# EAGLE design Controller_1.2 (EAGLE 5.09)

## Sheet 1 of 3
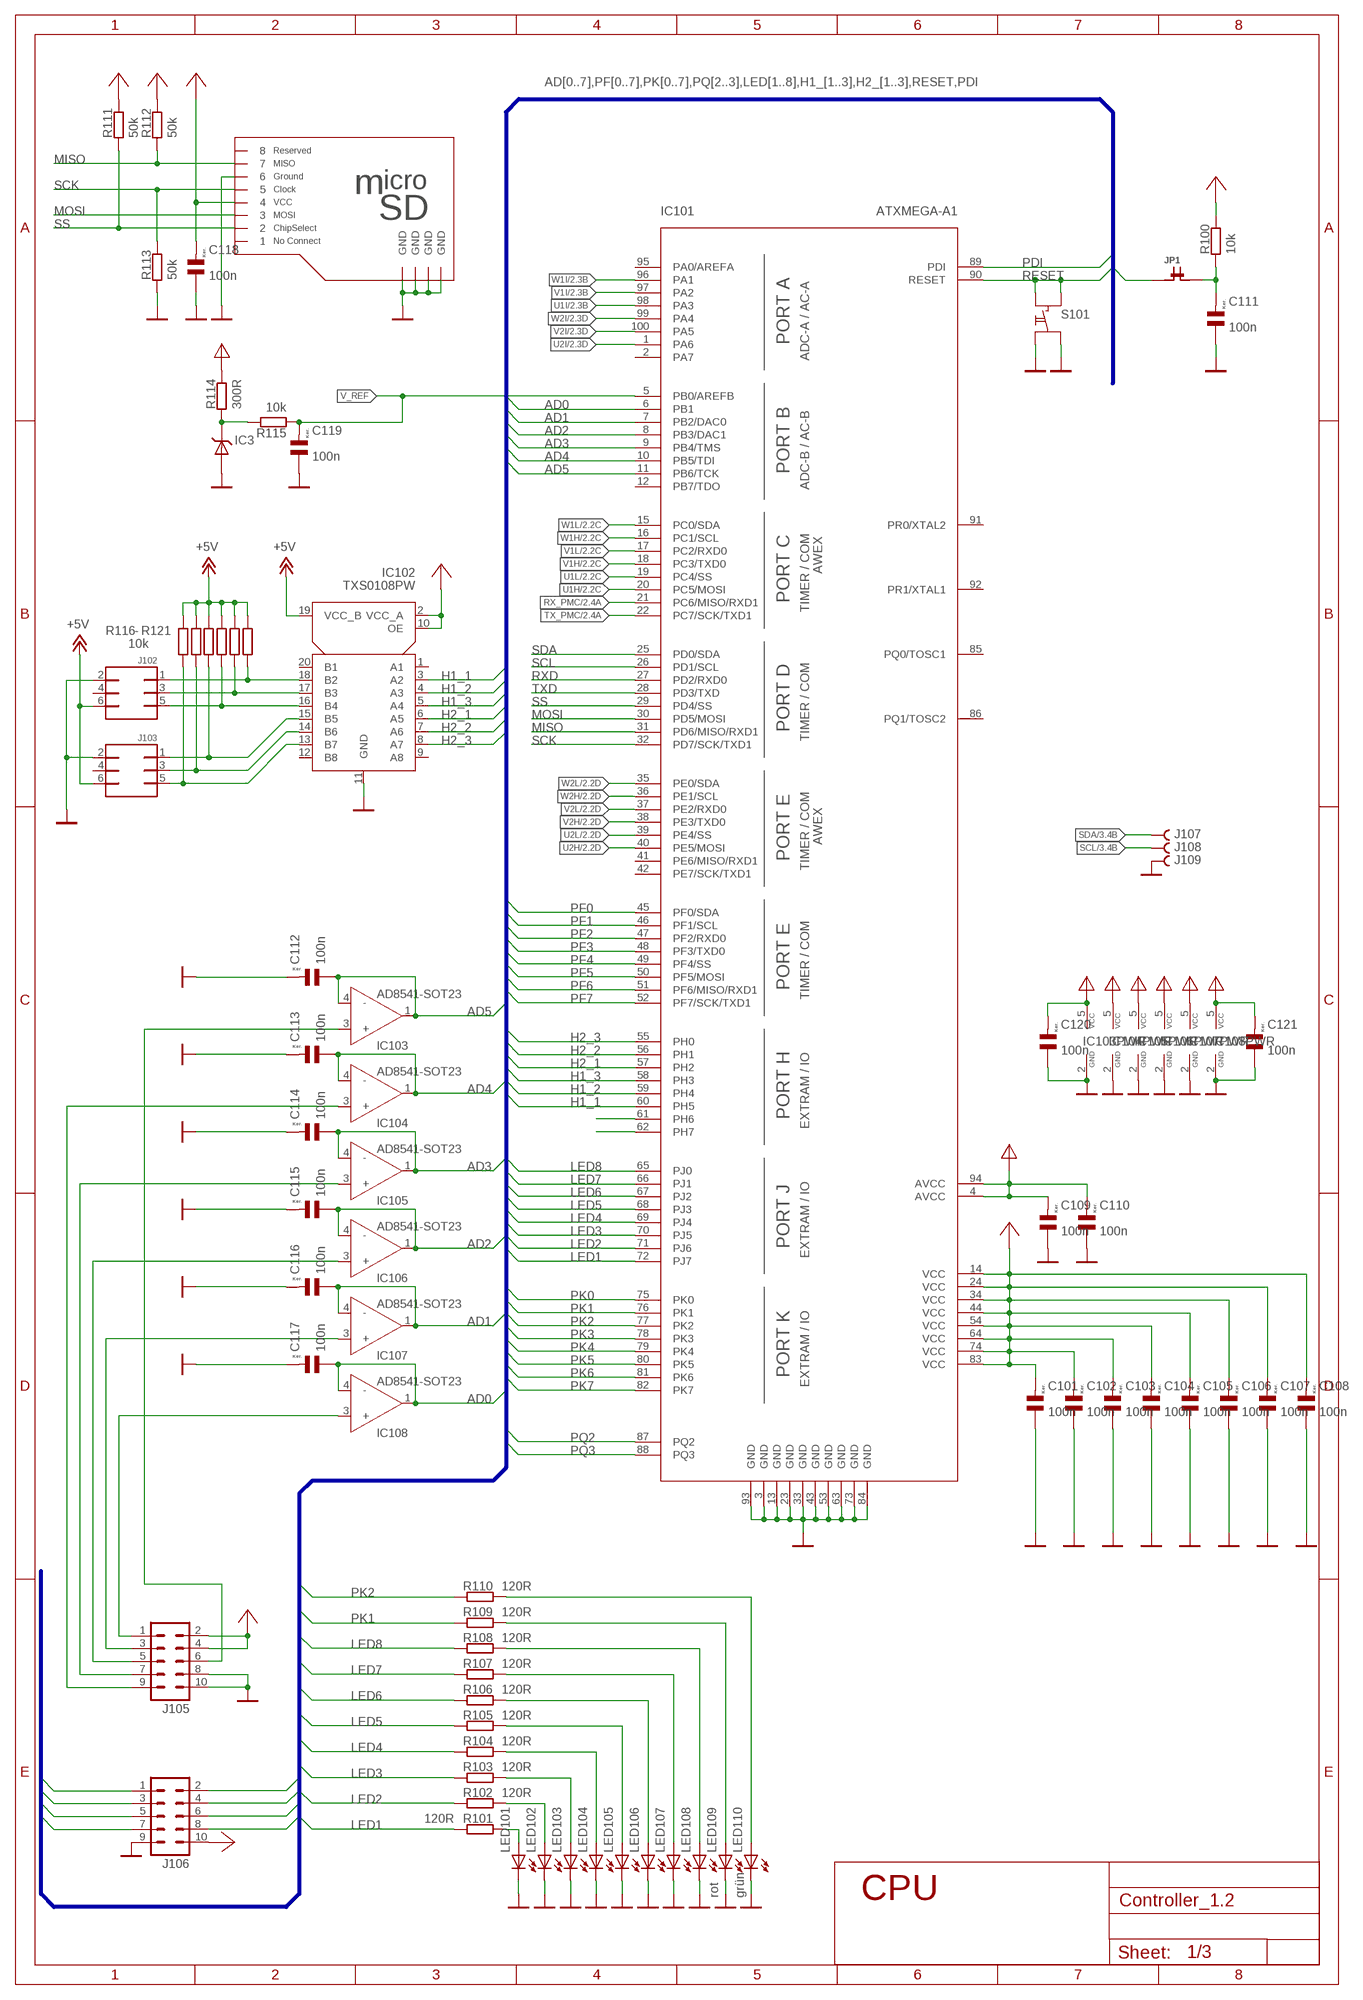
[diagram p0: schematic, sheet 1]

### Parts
C101  100n  C_KER_0805  [C0805K]
C102  100n  C_KER_0805  [C0805K]
C103  100n  C_KER_0805  [C0805K]
C104  100n  C_KER_0805  [C0805K]
C105  100n  C_KER_0805  [C0805K]
C106  100n  C_KER_0805  [C0805K]
C107  100n  C_KER_0805  [C0805K]
C108  100n  C_KER_0805  [C0805K]
C109  100n  C_KER_0805  [C0805K]
C110  100n  C_KER_0805  [C0805K]
C111  100n  C_KER_0805  [C0805K]
C112  100n  C_KER_0805  [C0805K]
C113  100n  C_KER_0805  [C0805K]
C114  100n  C_KER_0805  [C0805K]
C115  100n  C_KER_0805  [C0805K]
C116  100n  C_KER_0805  [C0805K]
C117  100n  C_KER_0805  [C0805K]
C118  100n  C_KER_0805  [C0805K]
C119  100n  C_KER_0805  [C0805K]
C120  100n  C_KER_0805  [C0805K]
C121  100n  C_KER_0805  [C0805K]
IC3  LM4040  [SOT23]
IC101  ATXMEGA-A1  [TQFP100]
IC102  TXS0108PW  TXB0108PW  [TSSOP20]
IC103  AD8541-SOT23  [SOT23-5L]
IC104  AD8541-SOT23  [SOT23-5L]
IC105  AD8541-SOT23  [SOT23-5L]
IC106  AD8541-SOT23  [SOT23-5L]
IC107  AD8541-SOT23  [SOT23-5L]
IC108  AD8541-SOT23  [SOT23-5L]
J101  MICRO_SD_ST1  [JAE_ST1_MICOSD]
J102  SL3X2_ML6  [ML6]
J103  SL3X2_ML6  [ML6]
J105  ML10  [ML10]
J106  ML10  [ML10]
J107  PIN_PAD_10  [PAD_10]
J108  PIN_PAD_10  [PAD_10]
J109  PIN_PAD_10  [PAD_10]
JP1  JP1  [JP1]
LED101  LEDCHIP-LED1206  [CHIPLED_1206]
LED102  LEDCHIP-LED1206  [CHIPLED_1206]
LED103  LEDCHIP-LED1206  [CHIPLED_1206]
LED104  LEDCHIP-LED1206  [CHIPLED_1206]
LED105  LEDCHIP-LED1206  [CHIPLED_1206]
LED106  LEDCHIP-LED1206  [CHIPLED_1206]
LED107  LEDCHIP-LED1206  [CHIPLED_1206]
LED108  LEDCHIP-LED1206  [CHIPLED_1206]
LED109  rot  LEDCHIP-LED1206  [CHIPLED_1206]
LED110  grün  LEDCHIP-LED1206  [CHIPLED_1206]
R100  10k  R_0805  [R0805]
R101  120R  R_0805  [R0805]
R102  120R  R_0805  [R0805]
R103  120R  R_0805  [R0805]
R104  120R  R_0805  [R0805]
R105  120R  R_0805  [R0805]
R106  120R  R_0805  [R0805]
R107  120R  R_0805  [R0805]
R108  120R  R_0805  [R0805]
R109  120R  R_0805  [R0805]
R110  120R  R_0805  [R0805]
R111  50k  R_0805  [R0805]
R112  50k  R_0805  [R0805]
R113  50k  R_0805  [R0805]
R114  300R  R_0805  [R0805]
R115  10k  R_0805  [R0805]
R116  10k  R_0805  [R0805]
R117  10k  R_0805  [R0805]
R118  10k  R_0805  [R0805]
R119  10k  R_0805  [R0805]
R120  10k  R_0805  [R0805]
R121  10k  R_0805  [R0805]
S101  PHAP3301  [PHAP3301]

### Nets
+5V: IC102.19(VCC_B) J102.6 J103.6 R116.2 R117.2 R118.2 R119.2 R120.2 R121.2 ; also sheet 2,3
AD0: C117.1 IC101.6(PB1) IC108.1(O) IC108.4(-)
AD1: C116.1 IC101.7(PB2/DAC0) IC107.1(O) IC107.4(-)
AD2: C115.1 IC101.8(PB3/DAC1) IC106.1(O) IC106.4(-)
AD3: C114.1 IC101.9(PB4/TMS) IC105.1(O) IC105.4(-)
AD4: C113.1 IC101.10(PB5/TDI) IC104.1(O) IC104.4(-)
AD5: C112.1 IC101.11(PB6/TCK) IC103.1(O) IC103.4(-)
AVCC: C109.2 C110.2 C120.2 C121.2 IC101.4(AVCC) IC101.94(AVCC) IC103.5(VCC) IC104.5(VCC) IC105.5(VCC) IC106.5(VCC) IC107.5(VCC) IC108.5(VCC) R114.2 ; also sheet 2,3
FB1: IC101.61(PH6) ; also sheet 2
FB2: IC101.62(PH7) ; also sheet 2
GND: C101.1 C102.1 C103.1 C104.1 C105.1 C106.1 C107.1 C108.1 C109.1 C110.1 C111.1 C112.2 C113.2 C114.2 C115.2 C116.2 C117.2 C118.1 C119.1 C120.1 C121.1 IC3.2(-) IC101.3(GND) IC101.13(GND) IC101.23(GND) IC101.33(GND) IC101.43(GND) IC101.53(GND) IC101.63(GND) IC101.73(GND) IC101.84(GND) IC101.93(GND) IC102.11(GND) IC103.2(GND) IC104.2(GND) IC105.2(GND) IC106.2(GND) IC107.2(GND) IC108.2(GND) J101.6 J101.GND1(GND) J101.GND2(GND) J101.GND3(GND) J101.GND4(GND) J102.2 J103.2 J105.8 J105.10 J106.9 J109.P$1 LED101.C LED102.C LED103.C LED104.C LED105.C LED106.C LED107.C LED108.C LED109.C LED110.C R113.1 S101.3 S101.4 ; also sheet 2,3
H1_1: IC101.60(PH5) IC102.3(A2)
H1_2: IC101.59(PH4) IC102.4(A3)
H1_3: IC101.58(PH3) IC102.5(A4)
H2_1: IC101.57(PH2) IC102.6(A5)
H2_2: IC101.56(PH1) IC102.7(A6)
H2_3: IC101.55(PH0) IC102.8(A7)
LED1: IC101.72(PJ7) R101.2
LED2: IC101.71(PJ6) R102.2
LED3: IC101.70(PJ5) R103.2
LED4: IC101.69(PJ4) R104.2
LED5: IC101.68(PJ3) R105.2
LED6: IC101.67(PJ2) R106.2
LED7: IC101.66(PJ1) R107.2
LED8: IC101.65(PJ0) R108.2
MISO: IC101.31(PD6/MISO/RXD1) J101.7 R112.1
MOSI: IC101.30(PD5/MOSI) J101.3
N$1: LED107.A R107.1
N$2: LED108.A R108.1
N$11: IC3.1(+) R114.1 R115.2
N$14: LED109.A R109.1
N$15: LED110.A R110.1
N$16: C111.2 JP1.2 R100.1
N$21: IC107.3(+) J105.3
N$35: IC102.18(B2) J102.1 R121.1
N$36: IC102.16(B4) J102.5 R119.1
N$37: IC102.17(B3) J102.3 R120.1
N$39: IC102.15(B5) J103.1 R118.1
N$40: IC102.14(B6) J103.3 R117.1
N$41: IC102.13(B7) J103.5 R116.1
N$63: LED101.A R101.1
N$64: IC108.3(+) J105.1
N$65: IC106.3(+) J105.5
N$66: IC105.3(+) J105.7
N$67: IC104.3(+) J105.9
N$68: IC103.3(+) J105.6
N$70: LED102.A R102.1
N$71: LED103.A R103.1
N$72: LED104.A R104.1
N$73: LED105.A R105.1
N$74: LED106.A R106.1
PDI: IC101.89(PDI) ; also sheet 2
PF0: IC101.45(PF0/SDA) J106.1
PF1: IC101.46(PF1/SCL) J106.2
PF2: IC101.47(PF2/RXD0) J106.3
PF3: IC101.48(PF3/TXD0) J106.4
PF4: IC101.49(PF4/SS) J106.5
PF5: IC101.50(PF5/MOSI) J106.6
PF6: IC101.51(PF6/MISO/RXD1) J106.7
PF7: IC101.52(PF7/SCK/TXD1) J106.8
PK0: IC101.75(PK0)
PK1: IC101.76(PK1) R109.2
PK2: IC101.77(PK2) R110.2
PK3: IC101.78(PK3) ; also sheet 3
PK4: IC101.79(PK4)
PK5: IC101.80(PK5)
PK6: IC101.81(PK6)
PK7: IC101.82(PK7)
PQ2: IC101.87(PQ2)
PQ3: IC101.88(PQ3)
RESET: IC101.90(RESET) JP1.1 S101.1 S101.2 ; also sheet 2
RX_PMC: IC101.21(PC6/MISO/RXD1) ; also sheet 2
RXD: IC101.27(PD2/RXD0) ; also sheet 2
SCK: IC101.32(PD7/SCK/TXD1) J101.5 R113.2
SCL: IC101.26(PD1/SCL) J108.P$1 ; also sheet 3
SDA: IC101.25(PD0/SDA) J107.P$1 ; also sheet 3
SS: IC101.29(PD4/SS) J101.2 R111.1
TX_PMC: IC101.22(PC7/SCK/TXD1) ; also sheet 2
TXD: IC101.28(PD3/TXD) ; also sheet 2
U1H: IC101.20(PC5/MOSI) ; also sheet 2
U1I: IC101.98(PA3) ; also sheet 2
U1L: IC101.19(PC4/SS) ; also sheet 2
U2H: IC101.40(PE5/MOSI) ; also sheet 2
U2I: IC101.1(PA6) ; also sheet 2
U2L: IC101.39(PE4/SS) ; also sheet 2
V1H: IC101.18(PC3/TXD0) ; also sheet 2
V1I: IC101.97(PA2) ; also sheet 2
V1L: IC101.17(PC2/RXD0) ; also sheet 2
V2H: IC101.38(PE3/TXD0) ; also sheet 2
V2I: IC101.100(PA5) ; also sheet 2
V2L: IC101.37(PE2/RXD0) ; also sheet 2
V_REF: C119.2 IC101.5(PB0/AREFB) R115.1
VCC: C101.2 C102.2 C103.2 C104.2 C105.2 C106.2 C107.2 C108.2 C118.2 IC101.14(VCC) IC101.24(VCC) IC101.34(VCC) IC101.44(VCC) IC101.54(VCC) IC101.64(VCC) IC101.74(VCC) IC101.83(VCC) IC102.2(VCC_A) IC102.10(OE) J101.4 J105.2 J105.4 J106.10 R100.2 R111.2 R112.2 ; also sheet 2,3
W1H: IC101.16(PC1/SCL) ; also sheet 2
W1I: IC101.96(PA1) ; also sheet 2
W1L: IC101.15(PC0/SDA) ; also sheet 2
W2H: IC101.36(PE1/SCL) ; also sheet 2
W2I: IC101.99(PA4) ; also sheet 2
W2L: IC101.35(PE0/SDA) ; also sheet 2
Unconnected: IC101.2(PA7) IC101.12(PB7/TDO) IC101.41(PE6/MISO/RXD1) IC101.42(PE7/SCK/TXD1) IC101.85(PQ0/TOSC1) IC101.86(PQ1/TOSC2) IC101.91(PR0/XTAL2) IC101.92(PR1/XTAL1) IC101.95(PA0/AREFA) IC102.1(A1) IC102.9(A8) IC102.12(B8) IC102.20(B1) J101.1 J101.8 J102.4 J103.4

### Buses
AD[0..7],PF[0..7],PK[0..7],PQ[2..3],LED[1..8],H1_[1..3],H2_[1..3],RESET,PDI

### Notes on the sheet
- -
- CPU

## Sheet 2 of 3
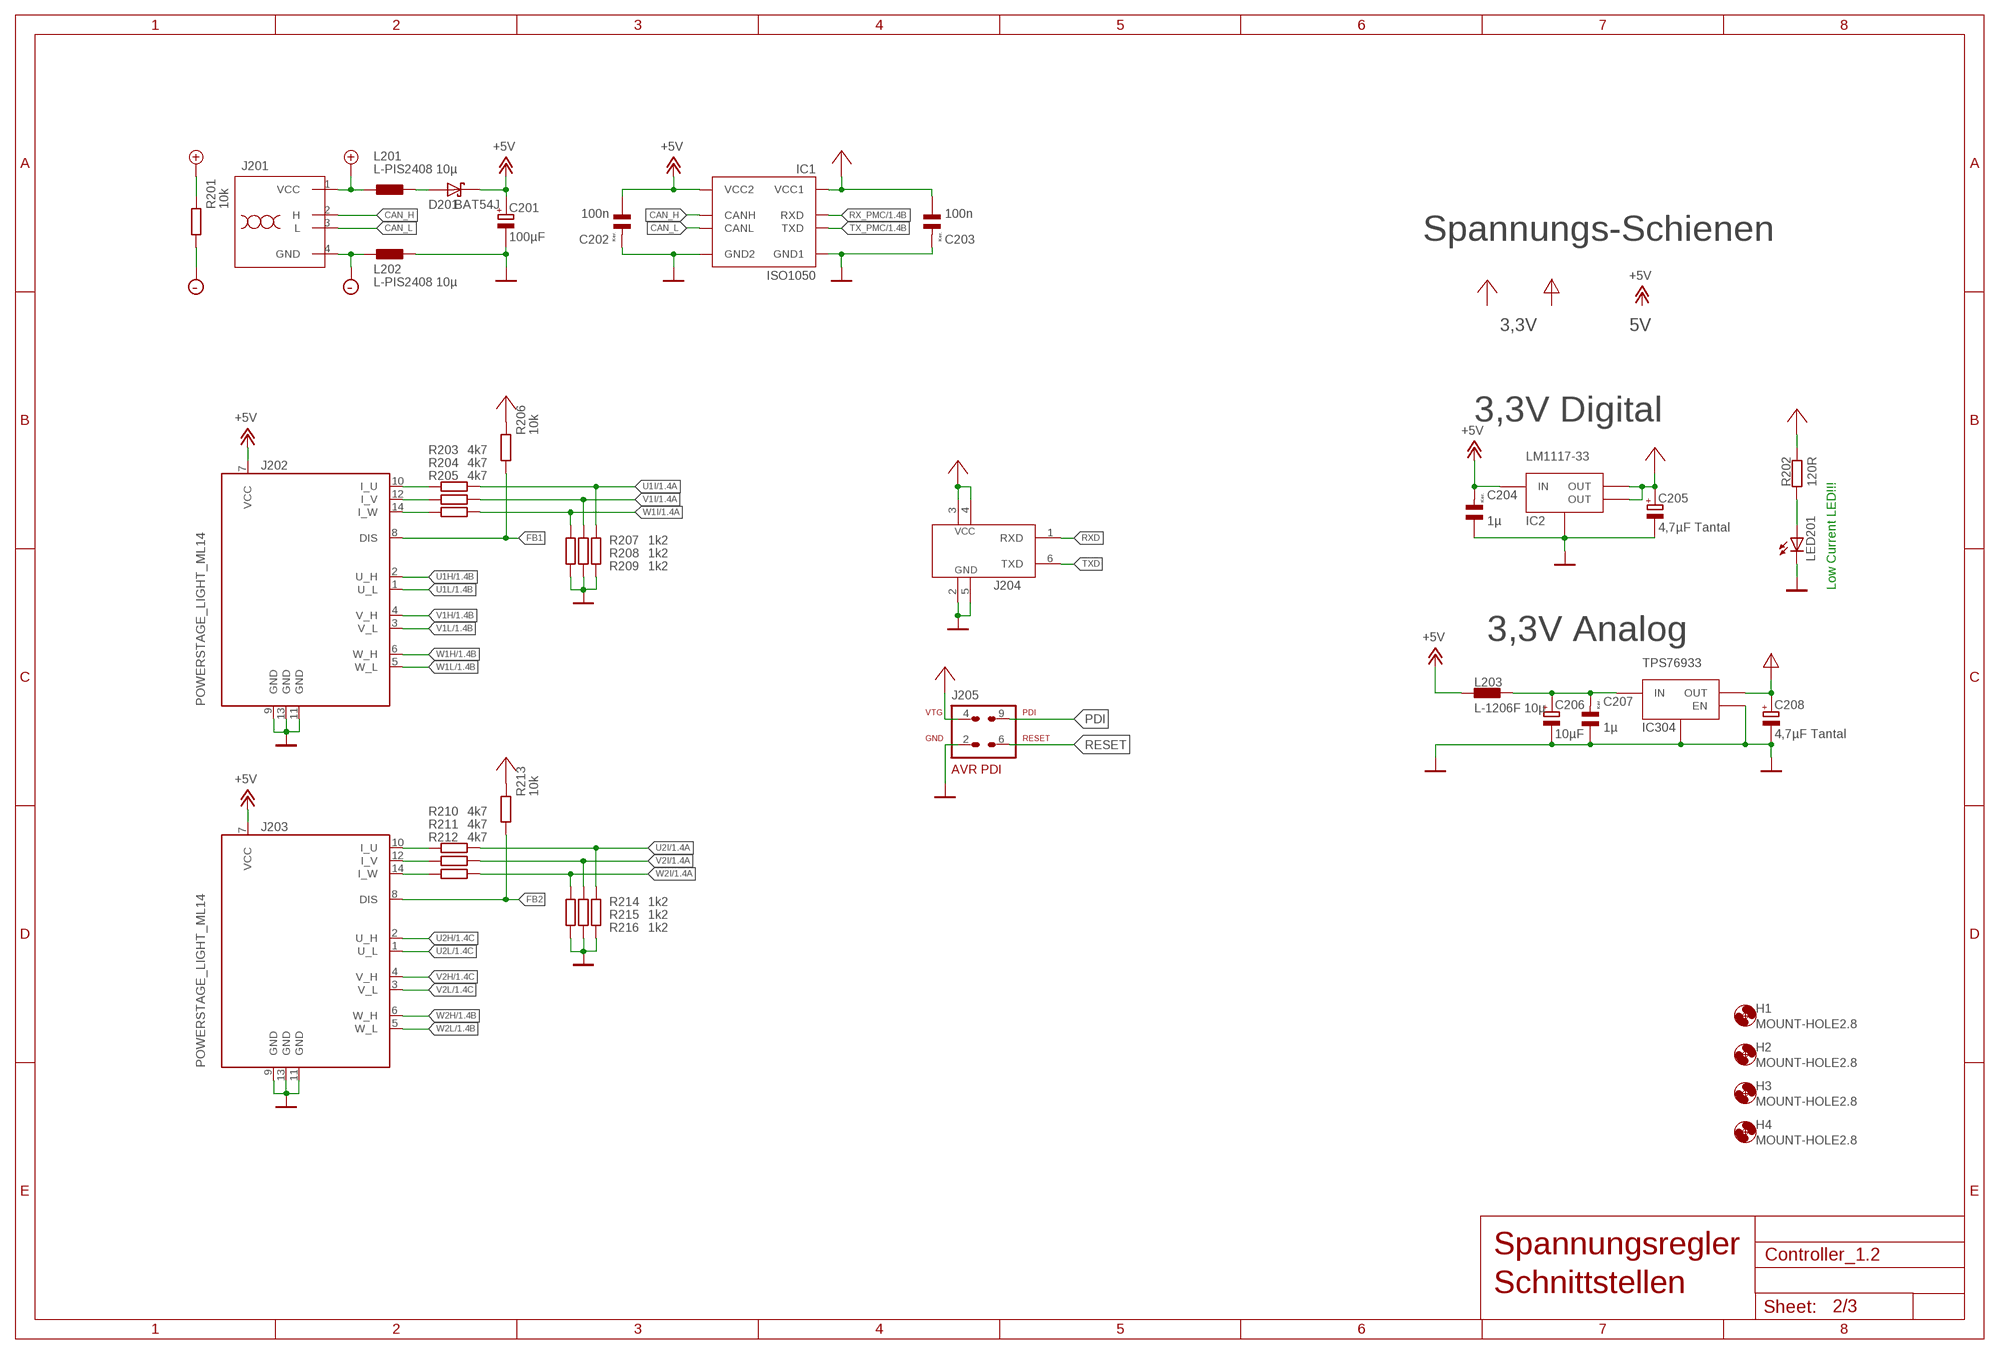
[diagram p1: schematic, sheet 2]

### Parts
C201  100µF  ELKO_SMD_06  [153CLV-0605]
C202  100n  C_KER_0805  [C0805K]
C203  100n  C_KER_0805  [C0805K]
C204  1µ  C_KER_1206  [C1206K]
C205  4,7µF Tantal  ELKO_SMD_B  [SMC_B]
C206  10µF  ELKO_SMD_04  [153CLV-0405]
C207  1µ  C_KER_0805  [C0805K]
C208  4,7µF Tantal  ELKO_SMD_A  [SMC_A]
D201  BAT54J  SCHOTTKY-DIODE-SOD323  [SOD323-W]
H1  MOUNT-HOLE2.8  [2,8]
H2  MOUNT-HOLE2.8  [2,8]
H3  MOUNT-HOLE2.8  [2,8]
H4  MOUNT-HOLE2.8  [2,8]
IC1  ISO1050  [PDSO8]
IC2  LM1117-33  [SOT223]
IC304  TPS76933  [SOT23-5L]
J201  PMC_AKL182  [AKL182-04]
J202  POWERSTAGE_LIGHT_ML14  [ML14]
J203  POWERSTAGE_LIGHT_ML14  [ML14]
J204  RS232_6PINHG  [ML6]
J205  AVR-PDIHG10  [ML10]
L201  L-PIS2408 10µ  L_PIS2408  [FASTRON_PIS2408]
L202  L-PIS2408 10µ  L_PIS2408  [FASTRON_PIS2408]
L203  L-1206F 10µ  L_1206  [R1206]
LED201  LEDCHIP-LED1206  [CHIPLED_1206]
R201  10k  R_0805  [R0805]
R202  120R  R_0805  [R0805]
R203  4k7  R_0805  [R0805]
R204  4k7  R_0805  [R0805]
R205  4k7  R_0805  [R0805]
R206  10k  R_0805  [R0805]
R207  1k2  R_0805  [R0805]
R208  1k2  R_0805  [R0805]
R209  1k2  R_0805  [R0805]
R210  4k7  R_0805  [R0805]
R211  4k7  R_0805  [R0805]
R212  4k7  R_0805  [R0805]
R213  10k  R_0805  [R0805]
R214  1k2  R_0805  [R0805]
R215  1k2  R_0805  [R0805]
R216  1k2  R_0805  [R0805]

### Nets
+5V: C201.+ C202.1 C204.2 D201.C IC1.8(VCC2) IC2.3(IN) J202.7(VCC) J203.7(VCC) L203.1 ; also sheet 1,3
AVCC: C208.+ IC304.5(OUT) ; also sheet 1,3
CAN_H: IC1.7(CANH) J201.2(H)
CAN_L: IC1.6(CANL) J201.3(L)
FB1: J202.8(DIS) R206.1 ; also sheet 1
FB2: J203.8(DIS) R213.1 ; also sheet 1
GND: C201.- C202.2 C203.2 C204.1 C205.- C206.- C207.1 C208.- IC1.4(GND1) IC1.5(GND2) IC2.1(GND) IC304.2(GND) IC304.3(EN) J202.9(GND) J202.11(GND) J202.13(GND) J203.9(GND) J203.11(GND) J203.13(GND) J204.2(GND) J204.5(GND) J205.2(GND) L202.2 LED201.C R207.1 R208.1 R209.1 R214.1 R215.1 R216.1 ; also sheet 1,3
N$3: D201.A L201.2
N$4: J202.10(I_U) R203.1
N$5: J202.12(I_V) R204.1
N$6: J202.14(I_W) R205.1
N$7: J203.12(I_V) R211.1
N$8: LED201.A R202.1
N$9: J203.14(I_W) R212.1
N$10: J203.10(I_U) R210.1
N$34: C206.+ C207.2 IC304.1(IN) L203.2
PDI: J205.9(PDI) ; also sheet 1
RESET: J205.6(RESET) ; also sheet 1
RX_PMC: IC1.2(RXD) ; also sheet 1
RXD: J204.1(RXD) ; also sheet 1
TX_PMC: IC1.3(TXD) ; also sheet 1
TXD: J204.6(TXD) ; also sheet 1
U1H: J202.2(U_H) ; also sheet 1
U1I: R203.2 R209.2 ; also sheet 1
U1L: J202.1(U_L) ; also sheet 1
U2H: J203.2(U_H) ; also sheet 1
U2I: R210.2 R216.2 ; also sheet 1
U2L: J203.1(U_L) ; also sheet 1
V1H: J202.4(V_H) ; also sheet 1
V1I: R204.2 R208.2 ; also sheet 1
V1L: J202.3(V_L) ; also sheet 1
V2H: J203.4(V_H) ; also sheet 1
V2I: R211.2 R215.2 ; also sheet 1
V2L: J203.3(V_L) ; also sheet 1
VCC: C203.1 C205.+ IC1.1(VCC1) IC2.2(OUT) IC2.4(OUT) J204.3(VCC) J204.4(VCC) J205.4(VTG) R202.2 R206.2 R213.2 ; also sheet 1,3
VS: J201.1(VCC) L201.1 R201.2
VSS: J201.4(GND) L202.1 R201.1
W1H: J202.6(W_H) ; also sheet 1
W1I: R205.2 R207.2 ; also sheet 1
W1L: J202.5(W_L) ; also sheet 1
W2H: J203.6(W_H) ; also sheet 1
W2I: R212.2 R214.2 ; also sheet 1
W2L: J203.5(W_L) ; also sheet 1

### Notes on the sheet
- Spannungs-Schienen
- 3,3V | 5V
- 3,3V Digital
- Low Current LED!!!
- 3,3V Analog
- Spannungsregler
- Schnittstellen

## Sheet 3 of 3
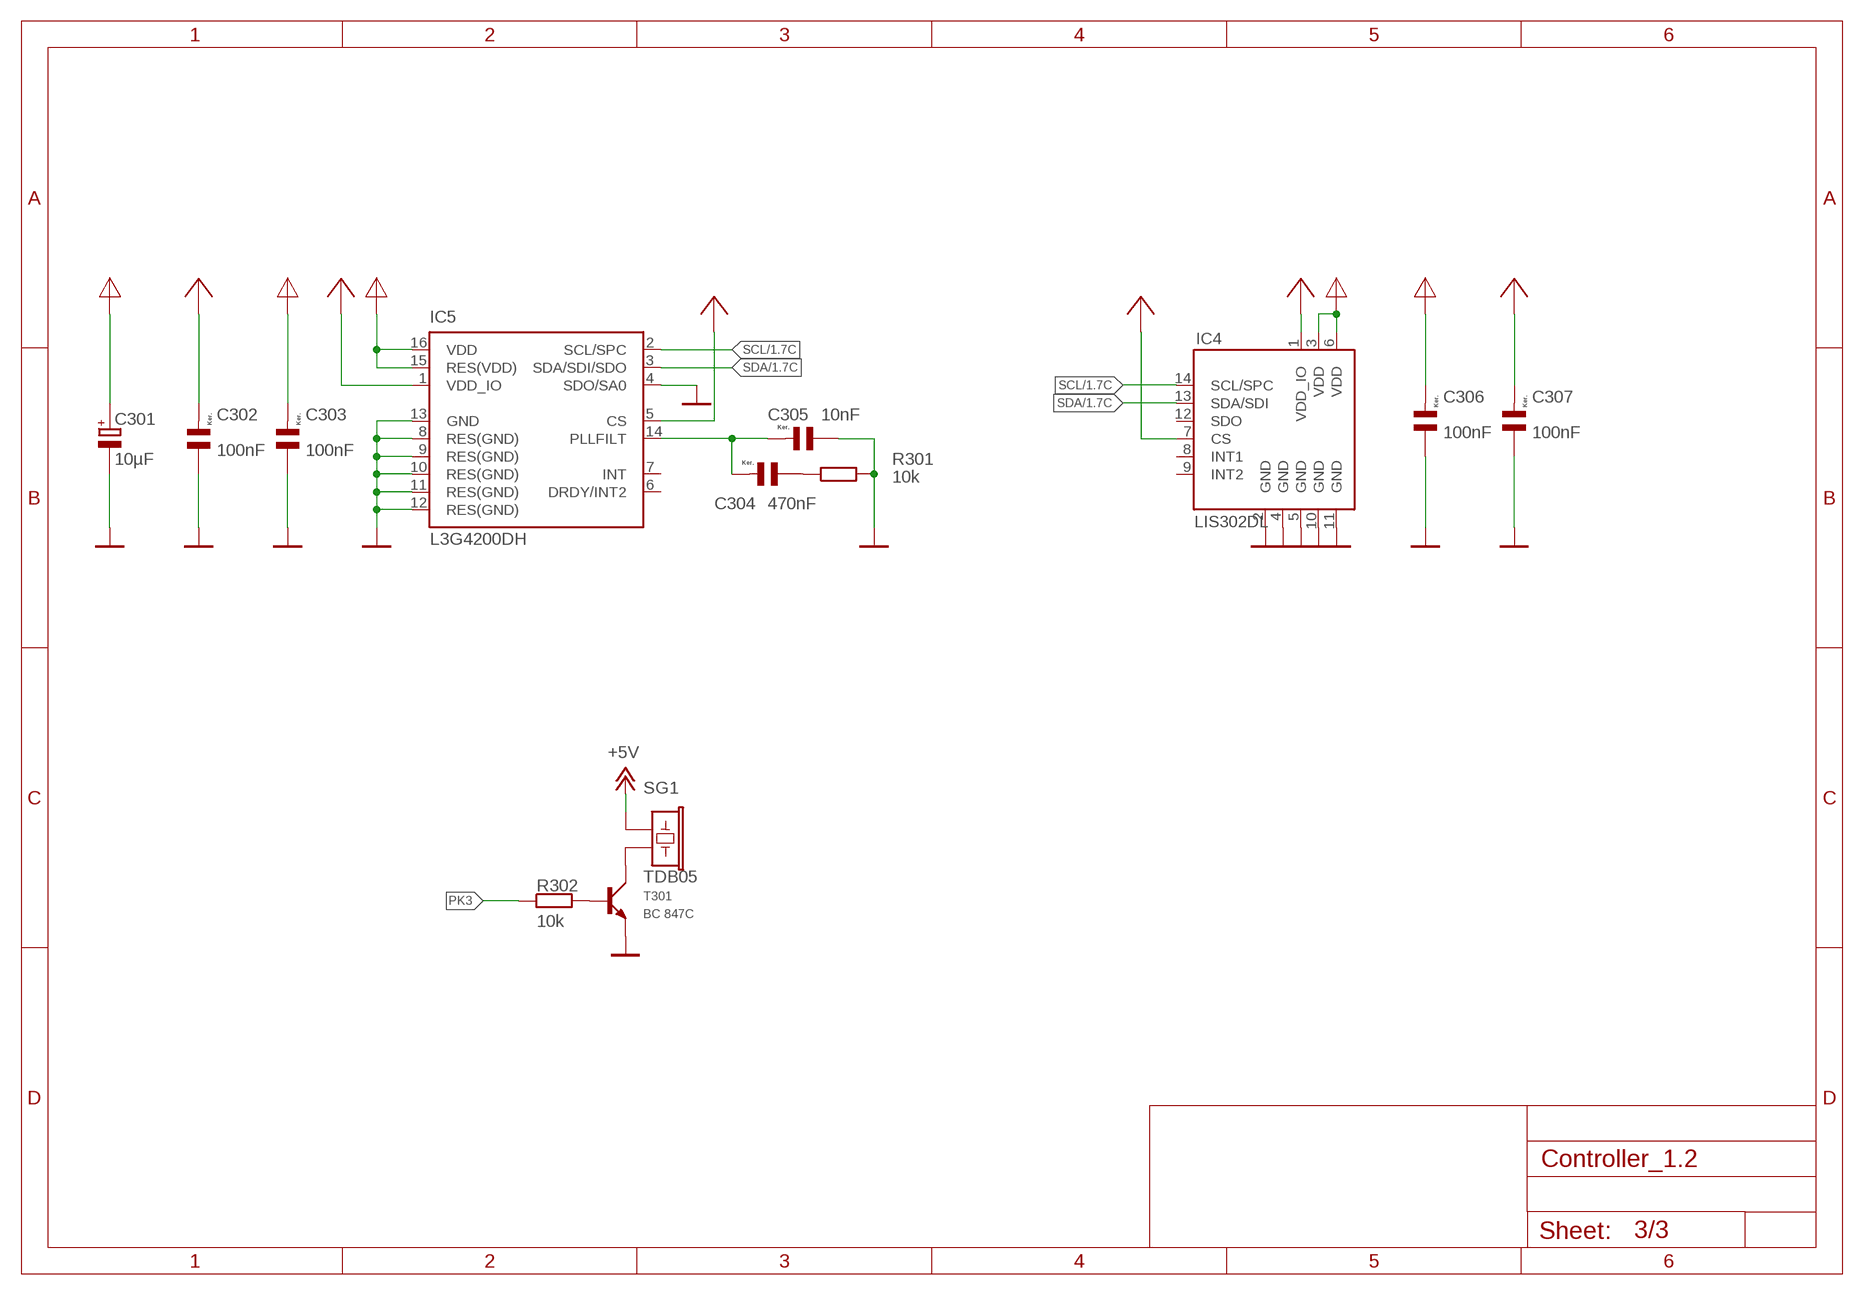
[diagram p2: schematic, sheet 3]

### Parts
C301  10µF  ELKO_SMD_04  [153CLV-0405]
C302  100nF  C_KER_0805  [C0805K]
C303  100nF  C_KER_0805  [C0805K]
C304  470nF  C_KER_0805  [C0805K]
C305  10nF  C_KER_0805  [C0805K]
C306  100nF  C_KER_0805  [C0805K]
C307  100nF  C_KER_0805  [C0805K]
IC4  LIS302DL  [LGA14]
IC5  L3G4200DH  [LGA-16L]
R301  10k  R_0805  [R0805]
R302  10k  R_0805  [R0805]
SG1  TDB05  SIGNALGEBER_TDB12  [TDB12]
T301  BC 847C  NPN_SOT23  [SOT23]

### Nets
+5V: SG1.2 ; also sheet 1,2
AVCC: C301.+ C303.2 C306.2 IC4.3(VDD) IC4.6(VDD) IC5.15(RES(VDD)) IC5.16(VDD) ; also sheet 1,2
GND: C301.- C302.1 C303.1 C305.1 C306.1 C307.1 IC4.2(GND) IC4.4(GND) IC4.5(GND) IC4.10(GND) IC4.11(GND) IC5.4(SDO/SA0) IC5.8(RES(GND)) IC5.9(RES(GND)) IC5.10(RES(GND)) IC5.11(RES(GND)) IC5.12(RES(GND)) IC5.13(GND) R301.2 T301.2(E) ; also sheet 1,2
N$12: C304.1 R301.1
N$13: C304.2 C305.2 IC5.14(PLLFILT)
N$17: SG1.1 T301.3(C)
N$18: R302.2 T301.1(B)
PK3: R302.1 ; also sheet 1
SCL: IC4.14(SCL/SPC) IC5.2(SCL/SPC) ; also sheet 1
SDA: IC4.13(SDA/SDI) IC5.3(SDA/SDI/SDO) ; also sheet 1
VCC: C302.2 C307.2 IC4.1(VDD_IO) IC4.7(CS) IC5.1(VDD_IO) IC5.5(CS) ; also sheet 1,2
Unconnected: IC4.8(INT1) IC4.9(INT2) IC4.12(SDO) IC5.6(DRDY/INT2) IC5.7(INT)

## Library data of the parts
C101-C121 C202-C204 C207 C302-C307 = lib-rcl:C_KER
C201 C205 C206 C208 C301 = lib-rcl:ELKO
D201 = lib-halbleiter:SCHOTTKY-DIODE
H1-H4 = holes:MOUNT-HOLE: MOUNTING HOLE with drill center marker
IC1 = lib-ic:ISO1050: ISOLATED CAN TRANSCEIVER
IC2 = lib-ic:LM1117-*: Alternativ auch TLV1117 von TI
IC3 = lib-ic:LM4040
IC4 = lib-ic:LIS302DL
IC5 = lib-ic:L3G4200DH*: L3G4200DH MEMS motion sensor - three-axis digital output gyroscope
IC101 = lib-avr:ATXMEGA-A1
IC102 = lib-ic:TXB0108?
IC103-IC108 = lib-ic:AD8541
IC304 = lib-ic:TPS769*
J101 = lib-misc:MICRO_SD
J102 J103 = lib-connectors:SL3X2?
J105 J106 = con-harting-ml:ML10: HARTING
J107-J109 = lib-connectors:PIN
J201 = lib-com:PMC: Poor-Mans-CAN
J202 J203 = lib-com:POWERSTAGE_LIGHT
J204 = lib-com:RS232_6PIN
J205 = lib-avr:AVR-PDI
JP1 = lib-connectors:JP1
L201-L203 = lib-rcl:L
LED101-LED110 LED201 = lib-halbleiter:LED
R100-R121 R201-R216 R301 R302 = lib-rcl:R: RESISTOR, European symbol
S101 = lib-switch:PHAP?*
SG1 = lib-misc:SIGNALGEBER: Piezo Summer
T301 = lib-halbleiter:NPN

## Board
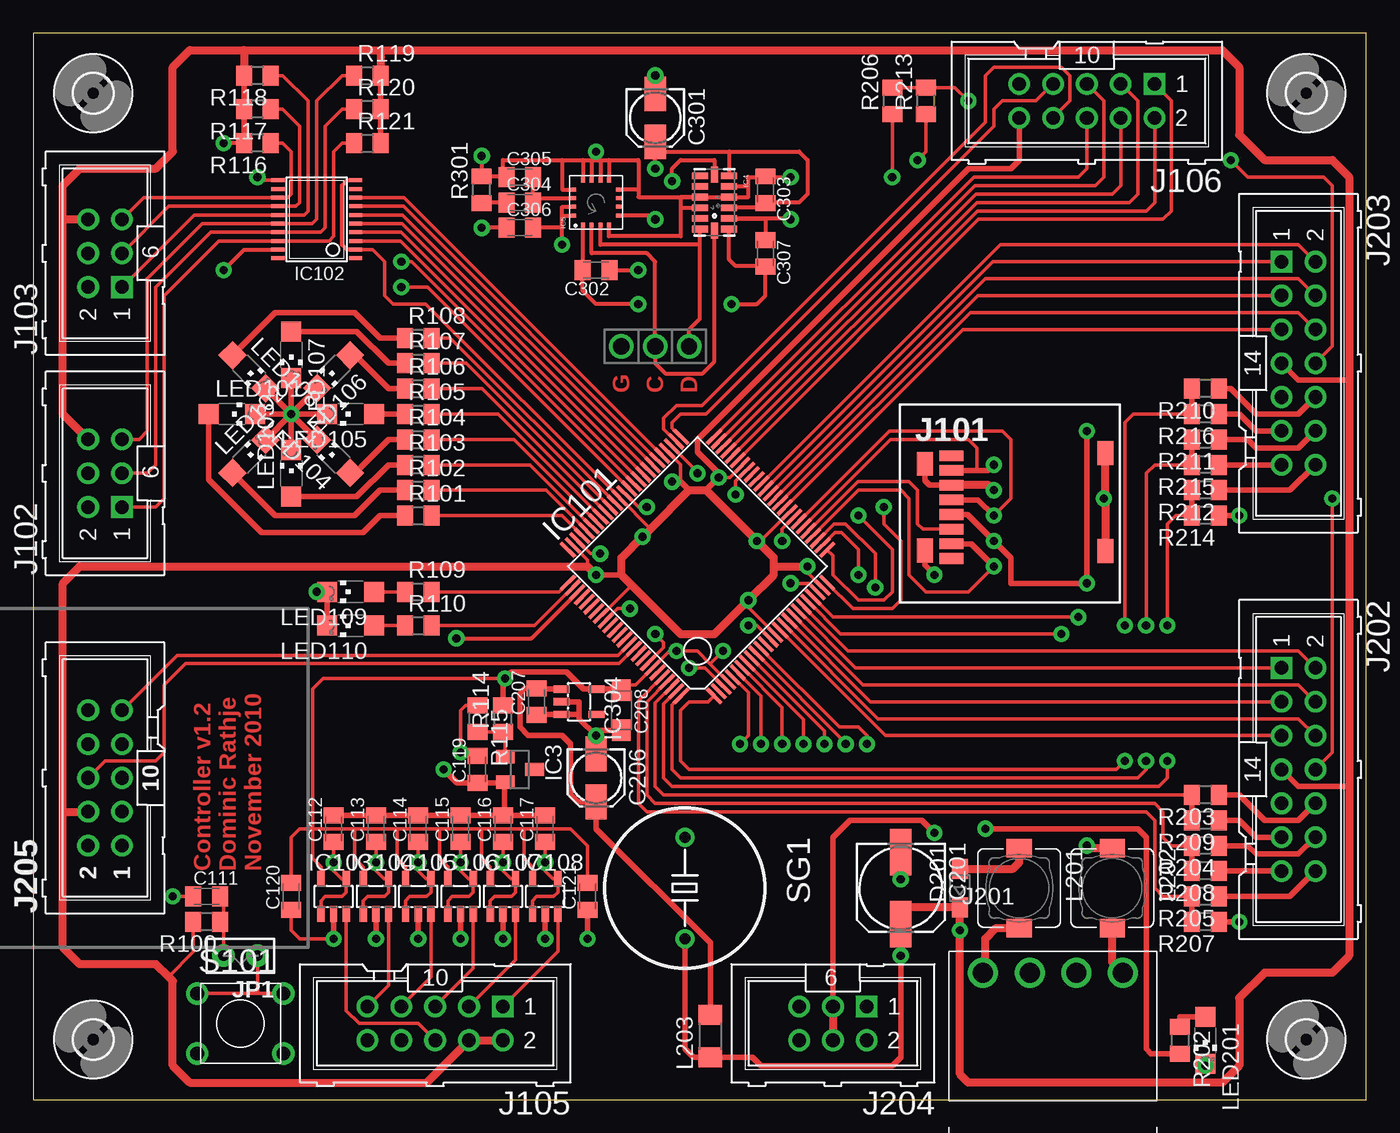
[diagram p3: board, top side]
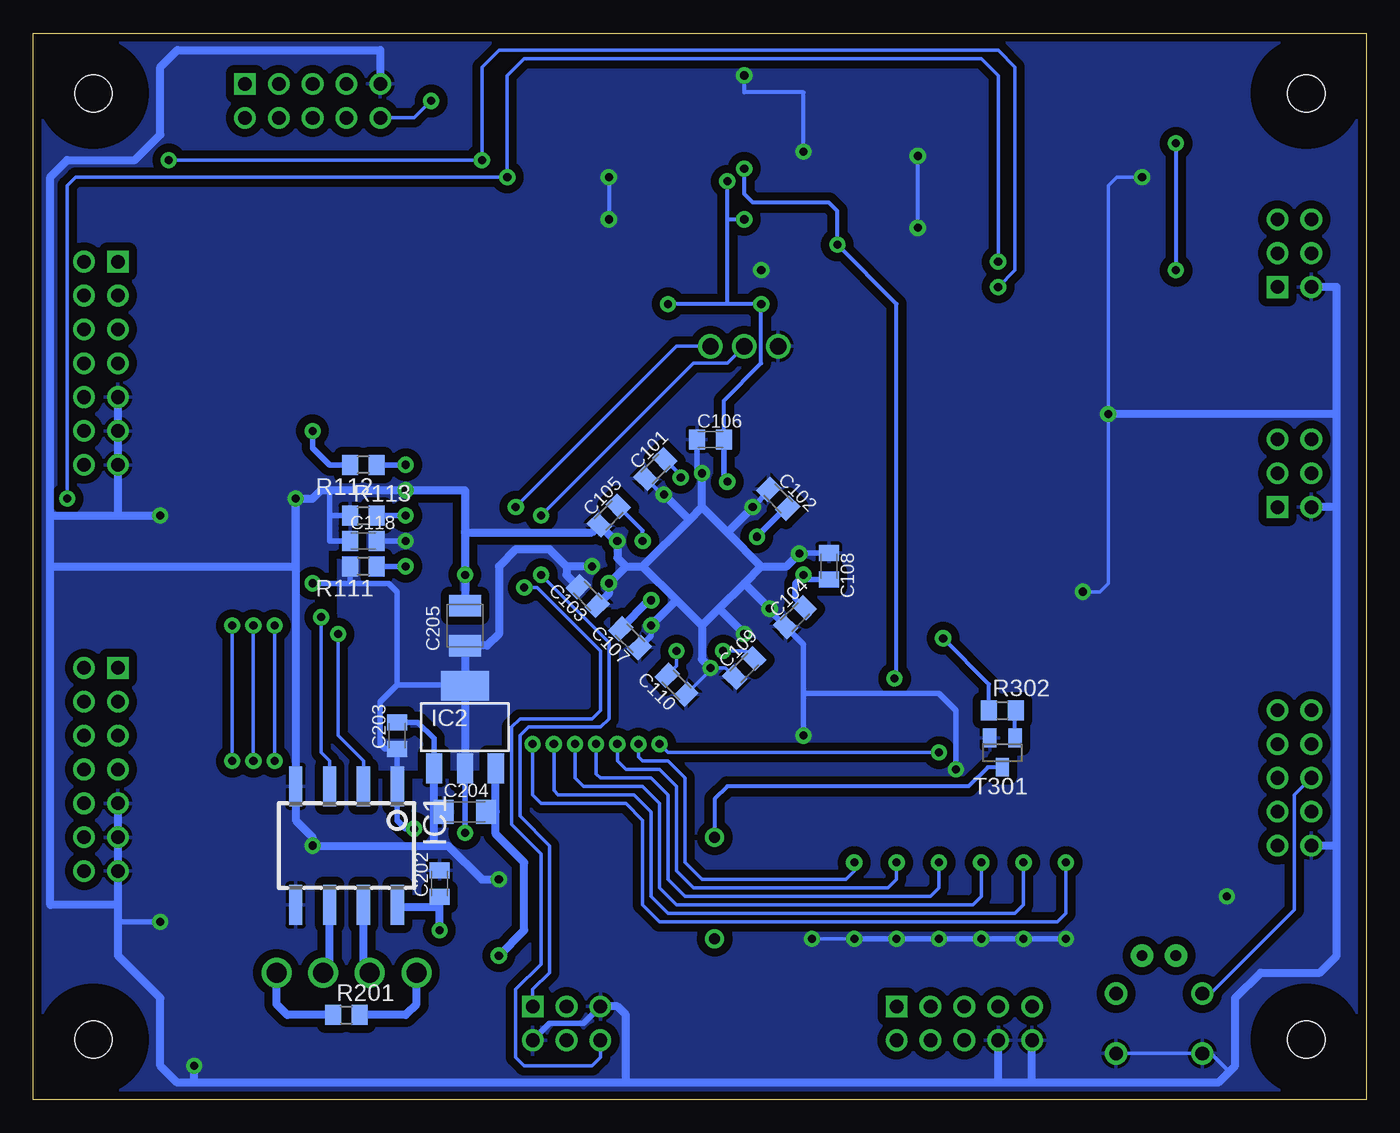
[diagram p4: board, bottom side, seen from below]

Size 100 x 80 mm. Coordinates in mm from the lower left corner, seen from the top.
Outline: 100,0 100,80 0,80 0,0 100,0
Copper layers (1*16): Top 0.0254mm / dielectric 1.4986mm / Bottom 0.0254mm
Design rules "uni_ulm": minimum track width 8mil, minimum drill 16mil, track to track 8mil, track to pad 8mil, pad to pad 8mil, via to via 8mil, smd to smd 8mil, copper to edge 20mil, drill to drill 8mil, minimum pad ring 12mil, minimum via ring 12mil, stop-mask expansion 4mil, vias tented up to drill 24mil, thermal gap 10mil

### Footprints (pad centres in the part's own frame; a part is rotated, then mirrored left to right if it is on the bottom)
C0805K = smd 1.2 x 1.5: 1 -1,0; 2 1,0
153CLV-0605 = smd 3.5 x 1.6: + 2.7,0; - -2.7,0
C1206K = smd 1.5 x 1.8: 1 -1.6,0; 2 1.6,0
SMC_B = smd 1.6 x 2.4: + -1.5,0; - 1.5,0
153CLV-0405 = smd 2.6 x 1.6: + 1.8,0; - -1.8,0
SMC_A = smd 1.6 x 1.4: + -1.5,0; - 1.5,0
SOD323-W = smd 1.5 x 1.2: A 1.45,0; C -1.45,0
2,8 = hole 2.8: 0,0
PDSO8 = smd 1 x 3: 1 -3.81,-4.445; 2 -1.27,-4.445; 3 1.27,-4.445; 4 3.81,-4.445; 5 3.81,4.445; 6 1.27,4.445; 7 -1.27,4.445; 8 -3.81,4.445
SOT223 = smd 1.219 x 2.235: 1 -2.311,-3.099; 2 0,-3.099; 3 2.311,-3.099 | smd 3.6 x 2.2: 4 0,3.099
SOT23 = smd 1 x 1.4: 1 -0.95,-1.1; 2 0.95,-1.1; 3 0,1.1
LGA14 = smd 0.5 x 1.2: 1 2,1.1; 2 1.2,1.1; 3 0.4,1.1; 4 -0.4,1.1; 5 -1.2,1.1; 6 -2,1.1; 8 -2,-1.1; 9 -1.2,-1.1; 10 -0.4,-1.1; 11 0.4,-1.1; 12 1.2,-1.1; 13 2,-1.1 | smd 1.2 x 0.5: 7 -2.1,0; 14 2.1,0
LGA-16L = smd 0.4 x 0.3: 1 -1.7,0.975; 2 -1.7,0.325; 3 -1.7,-0.325; 4 -1.7,-0.975; 9 1.7,-0.975; 10 1.7,-0.325; 11 1.7,0.325; 12 1.7,0.975 | smd 0.3 x 0.4: 5 -0.975,-1.7; 6 -0.325,-1.7; 7 0.325,-1.7; 8 0.975,-1.7; 13 0.975,1.7; 14 0.325,1.7; 15 -0.325,1.7; 16 -0.975,1.7
TQFP100 = smd 0.27 x 1.5: 1 -6,-7.75; 2 -5.5,-7.75; 3 -5,-7.75; 4 -4.5,-7.75; 5 -4,-7.75; 6 -3.5,-7.75; 7 -3,-7.75; 8 -2.5,-7.75; 9 -2,-7.75; 10 -1.5,-7.75; 11 -1,-7.75; 12 -0.5,-7.75; 13 0,-7.75; 14 0.5,-7.75; 15 1,-7.75; 16 1.5,-7.75; 17 2,-7.75; 18 2.5,-7.75; 19 3,-7.75; 20 3.5,-7.75; 21 4,-7.75; 22 4.5,-7.75; 23 5,-7.75; 24 5.5,-7.75; 25 6,-7.75; 51 6,7.75; 52 5.5,7.75; 53 5,7.75; 54 4.5,7.75; 55 4,7.75; 56 3.5,7.75; 57 3,7.75; 58 2.5,7.75; 59 2,7.75; 60 1.5,7.75; 61 1,7.75; 62 0.5,7.75; 63 0,7.75; 64 -0.5,7.75; 65 -1,7.75; 66 -1.5,7.75; 67 -2,7.75; 68 -2.5,7.75; 69 -3,7.75; 70 -3.5,7.75; 71 -4,7.75; 72 -4.5,7.75; 73 -5,7.75; 74 -5.5,7.75; 75 -6,7.75 | smd 1.5 x 0.27: 26 7.75,-6; 27 7.75,-5.5; 28 7.75,-5; 29 7.75,-4.5; 30 7.75,-4; 31 7.75,-3.5; 32 7.75,-3; 33 7.75,-2.5; 34 7.75,-2; 35 7.75,-1.5; 36 7.75,-1; 37 7.75,-0.5; 38 7.75,0; 39 7.75,0.5; 40 7.75,1; 41 7.75,1.5; 42 7.75,2; 43 7.75,2.5; 44 7.75,3; 45 7.75,3.5; 46 7.75,4; 47 7.75,4.5; 48 7.75,5; 49 7.75,5.5; 50 7.75,6; 76 -7.75,6; 77 -7.75,5.5; 78 -7.75,5; 79 -7.75,4.5; 80 -7.75,4; 81 -7.75,3.5; 82 -7.75,3; 83 -7.75,2.5; 84 -7.75,2; 85 -7.75,1.5; 86 -7.75,1; 87 -7.75,0.5; 88 -7.75,0; 89 -7.75,-0.5; 90 -7.75,-1; 91 -7.75,-1.5; 92 -7.75,-2; 93 -7.75,-2.5; 94 -7.75,-3; 95 -7.75,-3.5; 96 -7.75,-4; 97 -7.75,-4.5; 98 -7.75,-5; 99 -7.75,-5.5; 100 -7.75,-6
TSSOP20 = smd 0.305 x 0.991: 1 -2.925,-2.918; 2 -2.275,-2.918; 3 -1.625,-2.918; 4 -0.975,-2.918; 5 -0.325,-2.918; 6 0.325,-2.918; 7 0.975,-2.918; 8 1.625,-2.918; 9 2.275,-2.918; 10 2.925,-2.918; 11 2.925,2.918; 12 2.275,2.918; 13 1.625,2.918; 14 0.975,2.918; 15 0.325,2.918; 16 -0.325,2.918; 17 -0.975,2.918; 18 -1.625,2.918; 19 -2.275,2.918; 20 -2.925,2.918
SOT23-5L = smd 0.55 x 1.2: 1 -0.95,-1.3; 2 0,-1.3; 3 0.95,-1.3; 4 0.95,1.3; 5 -0.95,1.3
JAE_ST1_MICOSD = smd 1.8 x 0.8: 1 0,-3.85; 2 0,-2.75; 3 0,-1.65; 4 0,-0.55; 5 0,0.55; 6 0,1.65; 7 0,2.75; 8 0,3.85 | smd 1.2 x 1.8: GND1 11.55,-3.3; GND2 11.55,4.05; GND3 -2,-3.25; GND4 -2,3.25
ML6 = drill 1.016 pad 1.626 square: 1 -2.54,-1.27 | drill 1.016 pad 1.626 round: 2 -2.54,1.27; 3 0,-1.27; 4 0,1.27; 5 2.54,-1.27; 6 2.54,1.27
ML10 = drill 1.016 pad 1.626 square: 1 -5.08,-1.27 | drill 1.016 pad 1.626 round: 2 -5.08,1.27; 3 -2.54,-1.27; 4 -2.54,1.27; 5 0,-1.27; 6 0,1.27; 7 2.54,-1.27; 8 2.54,1.27; 9 5.08,-1.27; 10 5.08,1.27
PAD_10 = drill 1.219 pad 1.829 round: P$1 0,0
AKL182-04 = drill 1.5 pad 2.184 round: 1 -5.25,0; 2 -1.75,0; 3 1.75,0; 4 5.25,0
ML14 = drill 1.016 pad 1.626 square: 1 -7.62,-1.27 | drill 1.016 pad 1.626 round: 2 -7.62,1.27; 3 -5.08,-1.27; 4 -5.08,1.27; 5 -2.54,-1.27; 6 -2.54,1.27; 7 0,-1.27; 8 0,1.27; 9 2.54,-1.27; 10 2.54,1.27; 11 5.08,-1.27; 12 5.08,1.27; 13 7.62,-1.27; 14 7.62,1.27
ML10' = drill 1.016 pad 1.626 round: 1 -5.08,-1.27; 2 -5.08,1.27; 3 -2.54,-1.27; 4 -2.54,1.27; 5 0,-1.27; 6 0,1.27; 7 2.54,-1.27; 8 2.54,1.27; 9 5.08,-1.27; 10 5.08,1.27
JP1 = drill 0.813 pad 1.676 round: 1 -1.27,0; 2 1.27,0
FASTRON_PIS2408 = smd 1.4 x 1.9: 1 3,0; 2 -3,0
R1206 = smd 1.5 x 1.8: 1 -1.6,0; 2 1.6,0
CHIPLED_1206 = smd 1.5 x 1.5: A 0,-1.75; C 0,1.75
R0805 = smd 1.2 x 1.5: 1 -1,0; 2 1,0
PHAP3301 = drill 1.016 pad 1.676 round: 1 -2.235,-3.251; 2 -2.235,3.226; 3 2.261,-3.251; 4 2.261,3.226
TDB12 = drill 0.813 pad 1.422 round: 1 -3.79,0; 2 3.81,0

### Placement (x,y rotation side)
C101  53.33,47.31 45 bottom
C102  44.12,45.09 315 bottom
C103  58.41,37.78 135 bottom
C104  42.85,36.2 45 bottom
C105  56.82,43.81 45 bottom
C106  49.2,49.53 0 bottom
C107  55.23,34.61 135 bottom
C108  40.31,40.01 270 bottom
C109  46.66,32.38 45 bottom
C110  51.74,31.11 135 bottom
C111  13.01,15.24 0 top
C112  22.53,20.32 90 top
C113  25.71,20.32 90 top
C114  28.88,20.32 90 top
C115  32.05,20.32 90 top
C116  35.23,20.32 90 top
C117  38.4,20.32 90 top
C118  75.23,41.91 0 bottom
C119  33.32,24.77 90 top
C120  19.36,15.24 90 top
C121  41.58,15.24 90 top
C201  65.08,15.88 270 top
C202  69.52,16.19 90 bottom
C203  72.69,27.3 90 bottom
C204  67.61,21.59 0 bottom
C205  67.61,35.56 90 bottom
C206  42.21,24.13 270 top
C207  37.77,29.84 90 top
C208  44.12,29.21 270 top
C301  46.66,73.66 270 top
C302  42.21,62.23 180 top
C303  54.91,68.26 270 top
C304  36.5,67.31 0 top
C305  36.5,69.22 0 top
C306  36.5,65.41 0 top
C307  54.91,63.5 270 top
D201  69.52,15.88 90 top
H1  95.5,4.5 90 top
H2  95.5,75.5 90 top
H3  4.5,75.5 90 top
H4  4.5,4.5 90 top
IC1  76.5,19.05 180 bottom
IC2  67.61,27.94 0 bottom
IC3  36.5,24.77 270 top
IC4  51.1,67.31 270 top
IC5  42.21,67.31 90 top
IC101  49.83,40.01 45 top
IC102  21.26,66.04 90 top
IC103  22.53,15.24 0 top
IC104  25.71,15.24 0 top
IC105  28.88,15.24 0 top
IC106  32.05,15.24 0 top
IC107  35.23,15.24 0 top
IC108  38.4,15.24 0 top
IC304  40.95,29.84 270 top
J101  68.88,44.45 0 top
J102  5.38,46.99 90 top
J103  5.38,63.5 90 top
J105  30.15,5.71 180 top
J106  79.05,74.93 180 top
J107  49.2,56.52 90 top
J108  46.66,56.52 90 top
J109  44.12,56.52 90 top
J201  76.5,9.53 0 top
J202  94.92,24.77 270 top
J203  94.92,55.24 270 top
J204  59.99,5.71 180 top
J205  AVR-PDIHG10  [ML10']  5.38,24.13 90 top
JP1  15.54,10.79 180 top
L201  73.97,15.88 270 top
L202  80.95,15.88 270 top
L203  50.79,4.76 90 top
LED101  14.91,51.44 270 top
LED102  16.18,48.26 315 top
LED103  19.36,46.99 0 top
LED104  22.53,48.26 45 top
LED105  23.8,51.44 90 top
LED106  22.53,54.61 135 top
LED107  19.36,55.88 180 top
LED108  16.18,54.61 225 top
LED109  23.8,38.1 90 top
LED110  23.8,35.56 90 top
LED201  87.94,4.45 180 top
R100  13.01,13.34 180 top
R101  28.88,43.81 0 top
R102  28.88,45.72 0 top
R103  28.88,47.62 0 top
R104  28.88,49.53 0 top
R105  28.88,51.44 0 top
R106  28.88,53.34 0 top
R107  28.88,55.24 0 top
R108  28.88,57.15 0 top
R109  28.88,38.1 0 top
R110  28.88,35.56 0 top
R111  75.23,40.01 180 bottom
R112  75.23,47.62 180 bottom
R113  75.23,43.81 0 bottom
R114  35.23,28.57 90 top
R115  33.32,28.57 270 top
R116  16.82,71.75 180 top
R117  16.82,74.3 180 top
R118  16.82,76.83 180 top
R119  25.07,76.83 0 top
R120  25.07,74.3 0 top
R121  25.07,71.75 0 top
R201  76.5,6.35 0 bottom
R202  86.03,4.45 270 top
R203  87.94,22.86 180 top
R204  87.94,19.05 180 top
R205  87.94,15.24 180 top
R206  64.44,74.93 90 top
R207  87.94,13.34 180 top
R208  87.94,17.14 180 top
R209  87.94,20.95 180 top
R210  87.94,53.34 180 top
R211  87.94,49.53 180 top
R212  87.94,45.72 180 top
R213  66.98,74.93 90 top
R214  87.94,43.81 180 top
R215  87.94,47.62 180 top
R216  87.94,51.44 180 top
R301  33.64,68.26 90 top
R302  27.29,29.21 0 bottom
S101  15.54,5.71 270 top
SG1  48.88,15.88 270 top
T301  27.29,26.04 180 bottom

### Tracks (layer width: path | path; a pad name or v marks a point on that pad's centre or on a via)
+5V  (via drill 0.61 pad 0.81)
  Top 0.305: IC102.19 15.81,63.77 v14.27,62.23 | R116.2 v14.27,71.75
  Top 0.406: J202.7 94.92,23.5 98.73,23.5 | J203.7 94.92,53.98 98.73,53.98 | R116.2 R117.2 R118.2 | R119.2 R120.2 R121.2 | v65.08,10.79 65.08,3.17 64.44,2.54 54.6,2.54 53.96,3.17 50.8,3.17 L203.1 49.53,3.16 48.88,3.81 SG1.2
  Top 0.61: v65.08,10.79 C201.+ 65.08,14.43 D201.C v69.52,12.7 69.52,1.91 70.16,1.27 89.21,1.27 90.47,2.54 90.47,7.62 92.38,9.53 97.46,9.53 98.73,10.79 98.73,23.5 98.73,53.98 98.73,69.22 97.46,70.48 92.38,70.48 90.47,72.39 90.47,77.47 89.21,78.74 26.07,78.74 | J102.6 2.21,51.44 2.21,66.04 | 2.21,66.04 2.21,68.58 3.48,69.85 9.19,69.85 10.46,71.12 10.46,77.47 11.74,78.74 15.82,78.74 | 15.82,78.74 R118.2 | 26.07,78.74 R119.2 | 15.82,78.74 26.07,78.74 | 2.21,66.04 J103.6
  Bottom 0.305: v14.27,71.75 v14.27,62.23
  Bottom 0.61: 65.3,21.59 65.3,19.91 63.17,17.78 63.17,12.7 v65.08,10.79 | 65.3,21.59 IC2.3 | 65.3,21.59 C204.2 | v69.52,12.7 D201.C | D201.C C202.1 | D201.C 72.52,14.43 IC1.8
AD0  (via drill 0.61 pad 0.81)
  Top 0.254: IC101.6 54.6,30.29 v54.6,26.67 | IC108.1 37.46,14.93 37.77,15.24 39.04,15.24 39.35,15.55 IC108.4 39.01,16.54 38.4,17.14 v38.4,17.78 C117.1
  Bottom 0.254: v54.6,26.67 54.6,25.72 54.28,25.4 52.38,25.4 51.1,24.13 51.1,17.78 49.83,16.51 39.04,16.51 38.4,17.14 v38.4,17.78
AD1  (via drill 0.61 pad 0.81)
  Top 0.254: IC101.7 56.18,29.41 v56.18,26.67 | IC107.1 34.28,14.93 34.6,15.24 35.86,15.24 36.18,15.55 IC107.4 35.83,16.54 35.23,17.14 v35.23,17.78 C116.1
  Bottom 0.254: v56.18,26.67 56.18,25.4 55.55,24.77 53.01,24.77 51.74,23.5 51.74,17.14 50.47,15.88 35.86,15.88 35.23,16.51 v35.23,17.78
AD2  (via drill 0.61 pad 0.81)
  Top 0.254: IC101.8 57.77,28.53 v57.77,26.67 | IC106.1 31.1,14.93 31.42,15.24 32.69,15.24 33,15.55 IC106.4 32.66,16.54 32.06,17.14 v32.06,17.78 C115.1
  Bottom 0.254: v57.77,26.67 57.77,24.45 57.46,24.13 53.64,24.13 52.38,22.86 52.38,16.51 51.1,15.24 32.69,15.24 32.06,15.88 v32.06,17.78
AD3  (via drill 0.61 pad 0.81)
  Top 0.254: IC101.9 59.36,27.65 v59.36,26.67 | IC105.1 27.93,14.93 28.25,15.24 29.51,15.24 29.83,15.55 IC105.4 29.48,16.54 28.88,17.14 v28.88,17.78 C114.1
  Bottom 0.254: v59.36,26.67 59.36,24.13 58.72,23.5 54.28,23.5 53.01,22.23 53.01,15.88 51.74,14.61 29.51,14.61 28.88,15.24 v28.88,17.78
AD4  (via drill 0.61 pad 0.81)
  Top 0.254: IC101.10 60.95,26.77 v60.95,26.67 | IC104.1 24.75,14.93 25.07,15.24 26.34,15.24 26.66,15.55 IC104.4 26.31,16.54 25.71,17.14 v25.71,17.78 C113.1
  Bottom 0.254: v60.95,26.67 60.95,23.18 60.63,22.86 54.92,22.86 53.64,21.59 53.64,15.24 52.38,13.97 26.34,13.97 25.71,14.61 v25.71,17.78
AD5  (via drill 0.61 pad 0.81)
  Top 0.254: IC103.1 21.58,14.93 21.89,15.24 23.16,15.24 23.48,15.55 IC103.4 23.14,16.54 22.53,17.14 v22.53,17.78 C112.1 | IC101.11 60.49,27.94 61.9,27.94 62.53,27.3 v62.53,26.67
  Bottom 0.254: v62.53,26.67 62.53,22.86 61.9,22.23 55.55,22.23 54.28,20.95 54.28,14.61 53.01,13.34 23.16,13.34 22.53,13.97 v22.53,17.78
AVCC  (via drill 0.61 pad 0.81)
  Top 0.254: 50.78,32.7 IC101.4 | 50.78,32.7 49.82,33.66 v48.25,33.66 47.73,33.66 IC101.94 45.19,31.11 44.12,31.11 C208.+ | 50.78,32.7 v51.74,33.66 | IC108.5 37.46,17.46 36.82,18.1 36.82,20.32 | IC103.5 21.58,17.46 20.94,18.1 20.94,20.32 | v35.39,31.59 21.74,31.59 20.94,30.8 20.94,20.32 | 20.94,20.32 24.12,20.32 | IC104.5 24.75,17.46 24.12,18.1 24.12,20.32 | 24.12,20.32 27.29,20.32 | IC105.5 27.93,17.46 27.29,18.1 27.29,20.32 | IC106.5 31.1,17.46 30.47,18.1 30.47,20.32 | IC107.5 34.28,17.46 33.64,18.1 33.64,20.32 | 33.64,20.32 36.82,20.32 | 30.47,20.32 33.64,20.32 | 27.29,20.32 30.47,20.32 | C121.2 41.58,19.05 40.31,20.32 36.82,20.32 | C120.2 19.35,19.68 19.99,20.32 20.94,20.32
  Top 0.305: 39.68,66.33 IC5.16 | IC5.15 39.68,66.98 39.68,66.33 | 39.68,65.41 C306.2 | 39.68,65.41 39.68,66.33 | IC4.3 54.92,66.91 C303.2 54.96,67.31 57.46,67.31 58.09,67.94 58.09,70.48 57.46,71.12 52.21,71.12 | 46.66,71.12 C301.+ | 46.66,71.12 52.21,71.12 | 52.21,71.12 IC4.6 | v39.68,64.14 39.68,65.41 | v46.66,69.85 46.66,71.12
  Top 0.406: C208.+ 44.12,30.8 IC304.5 41.26,30.8 39.99,32.07 35.86,32.07 v35.39,31.59 35.23,31.43 R114.2
  Bottom 0.254: C110.2 51.74,32.53 v51.74,33.66 | C109.2 46.52,33.66 v48.25,33.66
  Bottom 0.305: v46.66,69.85 46.66,67.94 46.03,67.31 40.31,67.31 39.68,66.67 v39.68,64.14 35.23,59.69 35.23,31.75 v35.39,31.59
CAN_H
  Bottom 0.61: IC1.7 75.24,10.01 J201.2
CAN_L
  Bottom 0.61: IC1.6 77.77,10.01 J201.3
FB1  (via drill 0.61 pad 0.81)
  Top 0.254: J202.8 97.46,26.04 v97.46,45.09 | IC101.61 28.39,62.87 v27.61,62.87 | v64.44,69.22 R206.1
  Bottom 0.254: v97.46,45.09 97.46,68.58 96.83,69.22 v64.44,69.22 64.44,76.83 63.17,78.11 28.88,78.11 27.61,76.83 v27.61,62.87
FB2  (via drill 0.61 pad 0.81)
  Top 0.254: IC101.62 29.59,60.96 v27.61,60.96 | J203.8 97.46,56.52 97.46,68.58 96.83,69.22 91.11,69.22 v89.84,70.48 | R213.1 66.98,71.12 v66.35,70.48
  Bottom 0.254: v27.61,60.96 26.34,62.23 26.34,77.47 27.61,78.74 65.08,78.74 66.35,77.47 v66.35,70.48 v89.84,70.48
GND  (via drill 0.61 pad 0.81)
  Top 0.254: IC101.13 54.28,35.56 v53.64,35.56 | IC101.63 45.39,44.45 v46.03,44.45 | IC101.3 50.38,32.38 v49.2,32.38 | IC101.93 47.29,33.93 47.29,34.29 v46.66,34.92 | IC101.33 56.18,42.82 v56.18,41.91 | IC101.84 43.83,36.83 v44.75,36.83 | IC101.73 41.81,40.96 v42.53,40.96 | IC101.23 58.18,38.73 v56.82,38.73 | IC101.53 49.83,47.08 v49.83,46.99 | IC101.43 52.69,46.4 v52.69,45.4 | IC102.11 17.07,68.97 v16.82,69.22 | C120.1 19.35,12.7 19.99,12.06 v22.53,12.06 | 22.53,38.1 LED109.C | C111.1 v10.46,15.24
  Top 0.305: 43.19,70.48 IC5.9 | 41.24,70.48 IC5.12 | 41.89,70.48 IC5.11 | 41.24,70.48 41.89,70.48 | 42.54,70.48 IC5.10 | 42.21,70.48 42.54,70.48 | 41.89,70.48 42.21,70.48 | 45.39,68.28 IC5.8 | 45.39,68.28 45.39,70.48 43.19,70.48 | IC5.13 39.68,68.28 39.68,70.48 | 39.68,70.48 41.24,70.48 | 39.68,70.48 35.23,70.48 35.23,69.22 C305.1 35.5,69.26 R301.2 v33.64,70.8 | C306.1 v33.64,65.41 | 42.54,70.48 43.19,70.48 | 42.21,70.48 v42.21,71.12 | v46.66,76.83 C301.- | 53.64,68.51 IC4.5 | 54.87,64.45 C307.1 54.92,66.11 IC4.2 56.82,66.11 v56.82,66.04 | 53.64,68.51 53.64,67.71 IC4.4 IC4.10 | 48.57,66.91 IC4.11 | IC4.10 48.57,67.71 48.57,66.91 | 53.64,68.51 53.64,69.22 54.87,69.22 C303.1 54.92,69.22 v56.82,69.22 | 43.19,62.26 C302.1 v45.39,62.23 | IC4.10 45.39,67.71 45.39,68.28 | IC5.4 43.19,64.77 48.57,64.77 48.57,66.91
  Top 0.406: v19.35,51.44 LED104.C | v19.35,51.44 LED105.C | v19.35,51.44 LED106.C | v19.35,51.44 LED107.C | v19.35,51.44 LED108.C | v19.35,51.44 LED101.C | v19.35,51.44 LED102.C | v19.35,51.44 LED103.C | v90.47,13.34 R207.1 | R209.1 90.47,20.95 91.74,19.68 J202.11 | R216.1 90.47,51.44 91.74,50.16 J203.11 | J203.13 R215.1 | v90.47,43.81 R214.1 | J202.13 R208.1 | J101.GND4 66.88,46.45 67.24,46.1 J101.6 | J101.GND3 66.88,40.1 v67.61,39.37 | v42.21,27.3 C206.- | C207.1 37.82,28.89 IC304.3 40.95,28.89 | 40.95,28.89 40.95,29.84 IC304.2 | v42.21,27.3 42.62,27.71 C208.- | 40.95,28.89 40.95,28.57 v42.21,27.3 | v30.78,24.77 31.78,23.77 C119.1 35.35,23.77 | 35.35,23.77 IC3.2 | C112.2 C113.2 C114.2 C115.2 C116.2 | C116.2 C117.2 | 35.35,23.77 35.35,21.44 C116.2 | v38.4,12.06 IC108.2 | v22.53,12.06 IC103.2 | v25.71,12.06 IC104.2 | v28.88,12.06 IC105.2 | v32.06,12.06 IC106.2 | v35.23,12.06 IC107.2 | v41.58,12.06 C121.1 | LED109.C LED110.C | v21.26,38.1 22.53,38.1
  Top 0.61: v87.94,2.54 LED201.C | J101.GND1 80.44,44.97 v80.32,45.09 80.44,45.2 J101.GND2 | J101.6 71.68,46.1 v72.06,45.72 | L202.2 79.22,18.88 v79.05,19.05 | v65.08,16.51 C201.-
  Bottom 0.254: C110.1 49.2,32.24 v49.2,32.38 48.07,32.38 C109.1 | v16.82,69.22 18.72,69.22 19.35,68.58 v19.35,51.44 19.35,38.73 19.99,38.1 v21.26,38.1 | S101.3 S101.4 | 10.46,2.26 10.46,1.91 | v38.4,12.06 v41.58,12.06
  Bottom 0.305: 56.33,41.91 v56.18,41.91 | C101.1 52.84,45.4 v52.69,45.4 | v33.64,65.41 v33.64,70.8 | v42.21,71.12 42.21,75.56 46.66,75.56 v46.66,76.83 | v56.82,69.22 v56.82,66.04 | S101.3 11.66,3.45 10.46,2.26
  Bottom 0.406: 93.65,13.34 v90.47,13.34 | 77.77,45.72 77.77,43.81 | 77.77,43.81 77.77,41.91 C118.1 | 77.77,43.81 R113.1 | C106.1 50.2,47.35 v49.83,46.99 | C102.1 44.83,45.65 v46.03,44.45 | C108.1 42.49,41.01 v42.53,40.96 | v44.75,36.83 44.75,36.69 C104.1 42.21,34.15 42.21,30.48 | C107.1 53.64,34.78 v53.64,35.56 | J204.2 61.27,5.71 58.72,5.71 J204.5 | C203.2 71.16,28.3 69.93,27.08 IC2.1 | 42.21,30.48 v42.21,27.3 | v30.78,24.77 30.78,29.21 32.06,30.48 42.21,30.48 | v38.4,12.06 v35.23,12.06 v32.06,12.06 v28.88,12.06 v25.71,12.06 v22.53,12.06
  Bottom 0.61: J103.2 2.21,60.96 2.21,51.44 | 2.21,44.45 2.21,51.44 | 2.21,44.45 J102.2 | 2.21,19.05 2.21,44.45 | 2.21,19.05 J205.2 | 2.21,51.44 v19.35,51.44 | 2.21,19.05 2.21,10.79 3.48,9.53 7.93,9.53 9.83,7.62 9.83,2.54 10.46,1.91 11.1,1.27 25.07,1.27 | J202.9 J202.11 J202.13 93.65,14.61 | 93.65,14.61 93.65,13.34 93.65,10.79 90.47,7.62 90.47,2.54 89.21,1.27 87.94,1.27 | J203.9 J203.11 J203.13 93.65,43.81 | 98.73,43.81 93.65,43.81 | 98.73,40.01 98.73,14.61 93.65,14.61 | 98.73,40.01 98.73,43.81 | 87.94,1.27 v87.94,2.54 | 93.65,43.81 v90.47,43.81 | J106.9 73.97,78.74 89.21,78.74 90.47,77.47 90.47,72.39 92.38,70.48 97.46,70.48 98.73,69.22 98.73,43.81 | 51.74,37.47 v53.64,35.56 | 54.28,40.01 51.74,37.47 | 54.28,40.01 50.79,43.5 | 50.79,43.5 49.83,44.45 | 49.83,44.45 47.93,42.55 | 47.93,42.55 45.39,40.01 | 48.57,36.83 46.66,38.73 | 45.39,40.01 46.66,38.73 | 49.83,35.56 48.57,36.83 | 51.74,37.47 49.83,35.56 | 55.55,40.01 v56.82,38.73 56.82,37.96 C103.1 | 55.55,40.01 54.28,40.01 | v56.18,41.91 56.18,40.64 55.55,40.01 | 49.83,44.45 v49.83,46.99 | 47.93,42.55 v46.03,44.45 | v42.53,40.96 43.49,40.01 45.39,40.01 | 46.66,38.73 v44.75,36.83 | 48.57,36.83 v46.66,34.92 | 50.79,43.5 v52.69,45.4 | 55.55,1.27 87.94,1.27 | 27.61,1.27 55.55,1.27 | 25.07,1.27 27.61,1.27 | v49.2,32.38 49.83,33.02 49.83,35.56 | 69.93,19.05 69.93,21.59 | 69.93,21.59 IC2.1 | 69.93,19.05 v79.05,19.05 79.05,19.68 80.32,20.95 IC1.4 v80.32,45.09 | 69.93,21.59 C204.1 | C205.- v67.61,39.37 67.61,42.55 | 56.33,41.91 C105.1 58.09,42.55 | v80.32,45.09 79.05,45.09 78.41,45.72 77.77,45.72 v72.06,45.72 67.61,45.72 67.61,42.55 | 69.93,19.05 68.88,19.05 66.35,16.51 v65.08,16.51 | J204.5 56.18,6.99 55.55,6.35 55.55,1.27
  Bottom 0.61: v80.32,45.09 80.32,40.01 98.73,40.01 | 67.61,42.55 58.09,42.55 | 58.09,42.55 | 25.07,1.27 J105.10 | 27.61,1.27 J105.8
  pour Bottom (isolate 0.61, rank 2): -0.33,-0.64 100.63,-0.64 100.63,80.64 -0.33,80.64
H1_1
  Top 0.254: IC102.3 27.55,64.42 IC101.60
H1_2
  Top 0.254: IC102.4 27.6,65.06 IC101.59
H1_3
  Top 0.254: IC101.58 27.66,65.72 IC102.5
H2_1
  Top 0.254: IC101.57 27.72,66.36 IC102.6
H2_2
  Top 0.254: IC101.56 27.77,67.02 IC102.7
H2_3
  Top 0.254: IC101.55 27.83,67.67 IC102.8
LED1
  Top 0.254: IC101.72 39.66,43.81 R101.2
LED2
  Top 0.254: IC101.71 38.46,45.72 R102.2
LED3
  Top 0.254: IC101.70 37.27,47.62 R103.2
LED4
  Top 0.254: IC101.69 36.07,49.53 R104.2
LED5
  Top 0.254: IC101.68 34.87,51.44 R105.2
LED6
  Top 0.254: IC101.67 33.67,53.34 R106.2
LED7
  Top 0.254: IC101.66 32.47,55.24 R107.2
LED8
  Top 0.254: IC101.65 31.28,57.15 R108.2
MISO  (via drill 0.61 pad 0.81)
  Top 0.254: IC101.31 64.31,49.53 70.16,49.53 70.79,48.9 70.79,47.2
  Top 0.406: J101.7 70.79,47.2 71.63,47.2 v72.06,47.62
  Bottom 0.406: v72.06,47.62 R112.1
MOSI
  Top 0.254: IC101.30 61.87,46.38 61.9,46.35 65.71,46.35 66.35,45.72 66.35,43.18 66.72,42.8 J101.3
N$1
  Top 0.406: LED107.A 24.27,57.63 26.66,55.24 R107.1
N$2
  Top 0.406: LED108.A 18.15,59.05 24.12,59.05 26.02,57.15 R108.1
N$3
  Top 0.61: D201.A 73.51,17.32 73.97,17.78 L201.2
N$4
  Top 0.406: R203.1 90.47,22.86 92.38,20.95 94.92,20.95 J202.10
N$5
  Top 0.406: R204.1 91.11,19.05 91.74,18.41 94.92,18.41 J202.12
N$6
  Top 0.406: R205.1 94.28,15.24 J202.14
N$7
  Top 0.406: R211.1 91.11,49.53 91.74,48.9 94.92,48.9 J203.12
N$8
  Top 0.406: R202.1 86.03,6.2 LED201.A
N$9
  Top 0.406: R212.1 94.28,45.72 J203.14
N$10
  Top 0.406: R210.1 89.84,53.34 91.74,51.44 94.92,51.44 J203.10
N$11
  Top 0.254: R115.2 R114.1 35.4,27.41 IC3.1
N$12
  Top 0.305: C304.1 33.64,67.31 R301.1
N$13
  Top 0.305: IC5.14 37.5,67.64 C304.2 C305.2
N$14
  Top 0.254: LED109.A R109.1
N$15
  Top 0.254: LED110.A R110.1
N$16
  Top 0.254: JP1.2 14.27,13.34 | 14.27,13.34 14.27,14.97 C111.2 | 14.27,13.34 R100.1
N$17
  Bottom 0.305: T301.3 28.39,24.93 29.83,23.5 47.93,23.5 48.88,22.54 SG1.1
N$18
  Bottom 0.305: T301.1 26.34,29.16 R302.2
N$21
  Top 0.254: IC107.3 36.18,10.47 J105.3
N$34
  Top 0.406: IC304.1 37.82,30.8 C207.2 36.86,30.84 36.5,30.48 36.5,27.94 37.14,27.3 39.68,27.3 40.31,26.67 40.31,22.86 40.84,22.33 C206.+ 42.21,20.32 50.79,11.75 L203.2
N$35
  Top 0.254: J102.1 9.19,44.45 9.83,45.09 9.83,60.33 13.92,64.42 IC102.18 22.18,64.42 22.53,64.77 22.53,71.12 23.16,71.75 R121.1
N$36
  Top 0.254: J102.5 7.93,49.53 8.56,50.16 8.56,61.59 12.68,65.72 IC102.16 20.94,65.72 21.26,66.04 21.26,74.93 23.16,76.83 R119.1
N$37
  Top 0.254: J102.3 8.56,46.99 9.19,47.62 9.19,60.96 13.3,65.06 IC102.17 21.55,65.06 21.89,65.41 21.89,73.03 23.16,74.3 R120.1
N$39
  Top 0.254: J103.1 12.06,66.36 IC102.15 20.32,66.36 20.62,66.67 20.62,74.93 18.72,76.83 R118.1
N$40
  Top 0.254: J103.3 10.17,67.02 IC102.14 19.69,67.02 19.99,67.31 19.99,73.03 18.72,74.3 R117.1
N$41
  Top 0.254: J103.5 8.28,67.67 IC102.13 19.07,67.67 19.35,67.94 19.35,71.12 18.72,71.75 R116.1
N$63
  Top 0.406: LED101.A 13.16,46.52 17.13,42.55 24.75,42.55 26.02,43.81 R101.1
N$64
  Top 0.254: IC108.3 39.35,11.11 J105.1
N$65
  Top 0.254: IC106.3 33,9.84 J105.5
N$66
  Top 0.254: IC105.3 29.83,9.21 J105.7
N$67
  Top 0.254: IC104.3 26.66,8.57 J105.9
N$68
  Top 0.254: IC103.3 23.48,6.67 24.44,5.71 28.88,5.71 J105.6
N$70
  Top 0.406: LED102.A 18.15,43.81 24.12,43.81 26.02,45.72 R102.1
N$71
  Top 0.406: LED103.A 24.27,45.24 26.66,47.62 R103.1
N$72
  Top 0.406: LED104.A 24.15,47.02 26.66,49.53 R104.1
N$73
  Top 0.406: LED105.A R105.1
N$74
  Top 0.406: LED106.A 24.15,55.85 26.66,53.34 R106.1
PDI
  Top 0.254: IC101.89 43.87,33.34 10.78,33.34 J205.9
PF0
  Top 0.254: IC101.45 70.92,66.04 84.76,66.04 85.39,66.67 85.39,74.93 J106.1
PF1
  Top 0.254: IC101.46 70.85,66.67 83.49,66.67 84.13,67.31 J106.2
PF2
  Top 0.254: IC101.47 70.78,67.31 82.22,67.31 82.86,67.94 82.86,74.93 J106.3
PF3
  Top 0.254: IC101.48 70.7,67.94 80.95,67.94 81.58,68.58 J106.4
PF4
  Top 0.254: IC101.49 70.63,68.58 79.68,68.58 80.32,69.22 80.32,74.93 J106.5
PF5
  Top 0.254: IC101.50 70.56,69.22 78.41,69.22 79.05,69.85 J106.6
PF6
  Top 0.254: IC101.51 47.93,50.4 47.93,50.8 48.57,51.44 50.47,51.44 72.06,73.03 72.06,74.3 72.69,74.93 75.24,74.93 J106.7
PF7
  Top 0.254: IC101.52 47.29,50.32 47.29,51.12 48.25,52.07 50.15,52.07 71.43,73.34 71.43,76.83 72.06,77.47 77.14,77.47 77.77,76.83 77.77,74.93 J106.8
PK1
  Top 0.254: IC101.76 39.44,38.1 R109.2
PK2
  Top 0.254: IC101.77 37.61,35.56 R110.2
PK3  (via drill 0.61 pad 0.81)
  Top 0.305: IC101.78 37.37,34.61 v31.74,34.61
  Bottom 0.305: R302.1 28.29,31.16 v31.74,34.61
RESET
  Top 0.254: 16.82,7.95 S101.2 | S101.1 16.82,7.95 | IC101.90 43.95,32.7 11.42,32.7 9.83,31.11 9.83,26.04 9.19,25.4 5.38,25.4 J205.6 | 16.82,7.95 JP1.1
  Bottom 0.254: J205.6 5.38,22.86 5.38,14.22 11.66,7.95 S101.1
RX_PMC  (via drill 0.61 pad 0.81)
  Top 0.254: IC101.21 60.57,34.92 v77.14,34.92
  Bottom 0.254: v77.14,34.92 77.14,27.3 75.24,25.4 IC1.2
RXD  (via drill 0.61 pad 0.81)
  Top 0.254: IC101.27 60.15,42.55 60.63,42.55 61.9,41.27 v61.9,39.37
  Bottom 0.254: J204.1 62.53,8.26 61.27,9.53 61.27,19.05 63.49,21.27 63.49,27.3 62.85,27.94 57.46,27.94 56.82,28.57 56.82,34.29 v61.9,39.37
SCK  (via drill 0.61 pad 0.81)
  Top 0.254: IC101.32 64.24,50.16 72.69,50.16 73.33,49.53 73.33,45.09 v72.06,43.81
  Top 0.406: J101.5 70.88,45 v72.06,43.81
  Bottom 0.406: v72.06,43.81 R113.2
SCL  (via drill 0.61 pad 0.81)
  Top 0.254: IC101.26 60,40.8 60,39.37 61.9,37.47 63.81,37.47 64.44,38.1 64.44,41.27 v61.9,43.81
  Top 0.305: IC4.14 51.1,55.37 50.22,54.48 47.42,54.48 46.66,55.24 J108.P$1 46.66,62.87 46.03,63.5 41.89,63.5 IC5.2
  Bottom 0.254: v61.9,43.81 50.47,55.24 47.93,55.24 J108.P$1
SDA  (via drill 0.61 pad 0.81)
  Top 0.254: IC101.25 61.5,36.83 64.44,36.83 65.08,37.47 65.08,41.91 63.81,43.18 v63.81,44.45
  Top 0.305: 50,64.14 IC4.13 | IC5.3 42.54,64.14 50,64.14 | J107.P$1 49.2,57.78 50,58.59 50,64.14
  Bottom 0.254: v63.81,44.45 51.74,56.52 J107.P$1
SS  (via drill 0.61 pad 0.81)
  Top 0.254: IC101.29 60.01,43.81 60.01,43.83 61.9,45.72 65.08,45.72 65.71,45.09 65.71,39.37 66.98,38.1 70.16,38.1 v72.06,40.01
  Top 0.406: J101.2 70.36,41.7 v72.06,40.01
  Bottom 0.406: v72.06,40.01 R111.1
TX_PMC  (via drill 0.61 pad 0.81)
  Top 0.254: IC101.22 60.01,36.2 v78.41,36.2
  Bottom 0.254: v78.41,36.2 78.41,26.04 77.77,25.4 IC1.3
TXD  (via drill 0.61 pad 0.81)
  Top 0.254: IC101.28 60.08,43.18 60.95,43.18 63.17,40.96 v63.17,38.42
  Bottom 0.254: J204.6 57.46,3.17 58.09,2.54 63.17,2.54 63.81,3.17 63.81,8.26 61.9,10.16 61.9,18.41 64.12,20.64 64.12,27.94 63.49,28.57 58.09,28.57 57.46,29.21 57.46,33.66 62.22,38.42 v63.17,38.42
U1H
  Top 0.254: IC101.20 61.13,33.66 94.92,33.66 J202.2
U1I
  Top 0.254: IC101.98 46.66,29.76 46.66,23.5 47.29,22.86 R203.2
  Top 0.406: R203.2 R209.2
U1L
  Top 0.254: IC101.19 61.7,32.38 J202.1
U2H
  Top 0.254: IC101.40 72.55,64.14 94.92,64.14 J203.2
U2I  (via drill 0.61 pad 0.81)
  Top 0.254: IC101.1 50.64,29.84 49.2,29.84 48.57,29.21 48.57,25.4 49.2,24.77 81.27,24.77 v81.9,25.4 | v81.9,35.56 81.9,50.8 82.54,51.44 R216.2
  Top 0.406: R216.2 R210.2
  Bottom 0.254: v81.9,25.4 v81.9,35.56
U2L
  Top 0.254: IC101.39 71.99,62.87 J203.1
V1H
  Top 0.254: IC101.18 62.26,31.11 94.92,31.11 J202.4
V1I
  Top 0.254: IC101.97 47.52,31.34 46.03,29.84 46.03,22.86 46.66,22.23 84.13,22.23 84.76,21.59 84.76,19.68 85.39,19.05 R204.2
  Top 0.406: R204.2 R208.2
V1L
  Top 0.254: IC101.17 62.82,29.84 J202.3
V2H
  Top 0.254: IC101.38 71.43,61.59 94.92,61.59 J203.4
V2I  (via drill 0.61 pad 0.81)
  Top 0.254: IC101.100 47.93,29.61 47.93,24.77 48.57,24.13 82.86,24.13 83.49,24.77 v83.49,25.4 | v83.49,35.56 83.49,46.99 84.13,47.62 R215.2
  Top 0.406: R215.2 R211.2
  Bottom 0.254: v83.49,25.4 v83.49,35.56
V2L
  Top 0.254: IC101.37 70.86,60.33 J203.3
V_REF  (via drill 0.61 pad 0.81)
  Top 0.254: IC101.5 53.64,30.54 53.64,27.3 v53.01,26.67 | C119.2 32.32,25.77 v32.06,26.04 32.06,29.21 32.42,29.57 R115.1
  Bottom 0.254: v53.01,26.67 52.38,26.04 v32.06,26.04
VCC  (via drill 0.61 pad 0.81)
  Top 0.254: IC101.54 48.57,47.64 48.57,46.35 | IC101.34 54.6,41.94 54.6,41.59 | IC101.83 44.75,38.46 44.75,38.73 | 46.34,42.86 46.27,42.86 IC101.64 29.44,59.69 26.98,59.69 26.34,60.33 26.34,62.87 25.44,63.77 IC102.2 | 53.33,37.15 53.4,37.15 | IC101.24 58.09,39.53 v58.09,40.01 | IC101.44 52.26,46.67 v51.42,46.67 | IC101.14 53.64,36.9 v53.64,37.47 | v70.16,74.93 69.16,75.93 R213.2 R206.2 | IC101.74 41.58,40.48 41.58,40.01 | R100.2 12.01,11.06 10.15,9.21
  Top 0.305: IC102.10 23.55,68.97 23.16,68.58 23.16,64.14 23.53,63.77 IC102.2 | IC4.1 52.21,63.03 52.69,62.55 54.87,62.55 C307.2 54.92,60.33 54.28,59.69 v52.38,59.69 | IC5.1 41.24,62.26 C302.2 41.21,60.69 42.21,59.69 v45.39,59.69 | IC4.7 51.1,70.48 48.57,70.48 47.93,69.85 v47.93,68.9 | IC5.5 46.36,66.33 v46.66,66.04
  Top 0.406: J101.4 70.07,43.9 v72.06,41.91 73.33,40.64 73.33,38.73 v79.05,38.73 v79.05,50.16 | 49.2,45.72 48.57,46.35 v47.93,46.35 | J106.10 73.97,70.48 73.33,69.85 70.16,69.85 49.83,49.53 49.83,48.58 51.42,46.99 v51.42,46.67 50.47,45.72 | v42.21,39.37 44.12,39.37 | J204.3 60,19.68 61.27,20.95 66.66,20.95 v67.61,20 | R202.2 83.86,3.44 83.49,3.81 83.49,19.68 82.86,20.32 v71.43,20.32
  Top 0.61: 55.55,40.01 55.55,39.37 v53.64,37.47 53.33,37.15 51.1,34.92 48.57,34.92 44.75,38.73 44.12,39.37 44.12,40.64 v45.71,42.23 46.34,42.86 49.2,45.72 50.47,45.72 v54.28,41.91 54.6,41.59 55.55,40.64 55.55,40.01 | 55.55,40.01 v58.09,40.01 | J204.3 J204.4 | 2.21,21.59 J205.4 | v42.21,39.37 41.58,40.01 3.48,40.01 2.21,38.73 2.21,21.59 | 2.21,21.59 2.21,11.43 3.48,10.16 9.19,10.16 10.15,9.21 10.46,8.89 10.46,2.54 11.74,1.27 29.51,1.27 J105.4 J105.2
  Bottom 0.254: v70.16,74.93 71.43,73.66 J106.10
  Bottom 0.305: C105.2 54.28,42.69 v54.28,41.91 | C101.2 51.42,46.82 v51.42,46.67 | 47.93,59.69 v45.39,59.69 45.39,55.24 48.2,52.44 C106.2 | 47.93,59.69 v52.38,59.69 | 47.93,59.69 47.93,66.04 | 47.93,66.04 v47.93,68.9 | 47.93,66.04 v46.66,66.04
  Bottom 0.406: v79.05,50.16 79.05,48.9 77.77,47.62 R112.2 | v72.06,41.91 C118.2 | C106.2 48.2,46.62 v47.93,46.35 | C102.2 43.56,44.38 v45.71,42.23 | C108.2 41.85,39.01 v42.21,39.37 42.85,38.73 42.85,37.61 C104.2 | v53.64,37.47 53.79,37.47 | 72.69,31.11 72.69,38.1 73.33,38.73 76.24,38.73 | IC2.4 67.61,31.11 72.69,31.11 | 76.24,38.73 R111.2 | 76.24,38.73 v79.05,38.73 | IC2.2 v67.61,20 | 72.69,31.11 73.97,29.84 73.97,26.67 73.6,26.3 C203.1 IC1.1 72.69,20.95 72.06,20.32 v71.43,20.32
  Bottom 0.61: 53.79,37.47 C107.2 | IC2.2 IC2.4 C205.+ 65.94,34.06 65.08,34.92 65.08,40.01 63.81,41.27 61.27,41.27 60,40.01 | C103.2 60,39.37 60,40.01 | v58.09,40.01 60,40.01
  pour Bottom (isolate 0.61, no thermals): 56.82,24.77 77.14,24.77 77.14,45.09 68.25,45.09 68.25,41.91 56.82,41.91
VS
  Top 0.61: L201.1 72.24,12.88 71.43,12.06 71.43,9.7 J201.1
  Bottom 0.61: R201.2 72.06,6.35 71.25,7.16 J201.1
VSS
  Top 0.61: L202.1 80.95,10.33 J201.4
  Bottom 0.61: R201.1 80.95,6.35 81.75,7.16 J201.4
W1H
  Top 0.254: IC101.16 63.39,28.57 94.92,28.57 J202.6
W1I
  Top 0.254: IC101.96 45.39,29.9 45.39,22.23 46.03,21.59 83.49,21.59 84.13,20.95 84.13,15.88 84.76,15.24 R205.2
  Top 0.406: R205.2 R207.2
W1L
  Top 0.254: IC101.15 63.95,27.3 J202.5
W2H
  Top 0.254: IC101.36 70.3,59.05 94.92,59.05 J203.6
W2I  (via drill 0.61 pad 0.81)
  Top 0.254: IC101.99 47.29,29.69 47.29,24.13 47.93,23.5 84.44,23.5 85.08,24.13 v85.08,25.4 | v85.08,35.56 85.08,43.18 85.71,43.81 R214.2
  Top 0.406: R214.2 R212.2
  Bottom 0.254: v85.08,25.4 v85.08,35.56
W2L
  Top 0.254: IC101.35 69.74,57.78 J203.5

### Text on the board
Top: G | C | D | Controller v1.2 | Dominic Rathje | November 2010
Measures: alle Maße in mm | (100,80) | (0,80) | (0,0) | (100,0)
